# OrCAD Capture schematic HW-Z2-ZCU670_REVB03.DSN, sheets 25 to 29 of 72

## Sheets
25 025 USB UART JTAG: size Custom
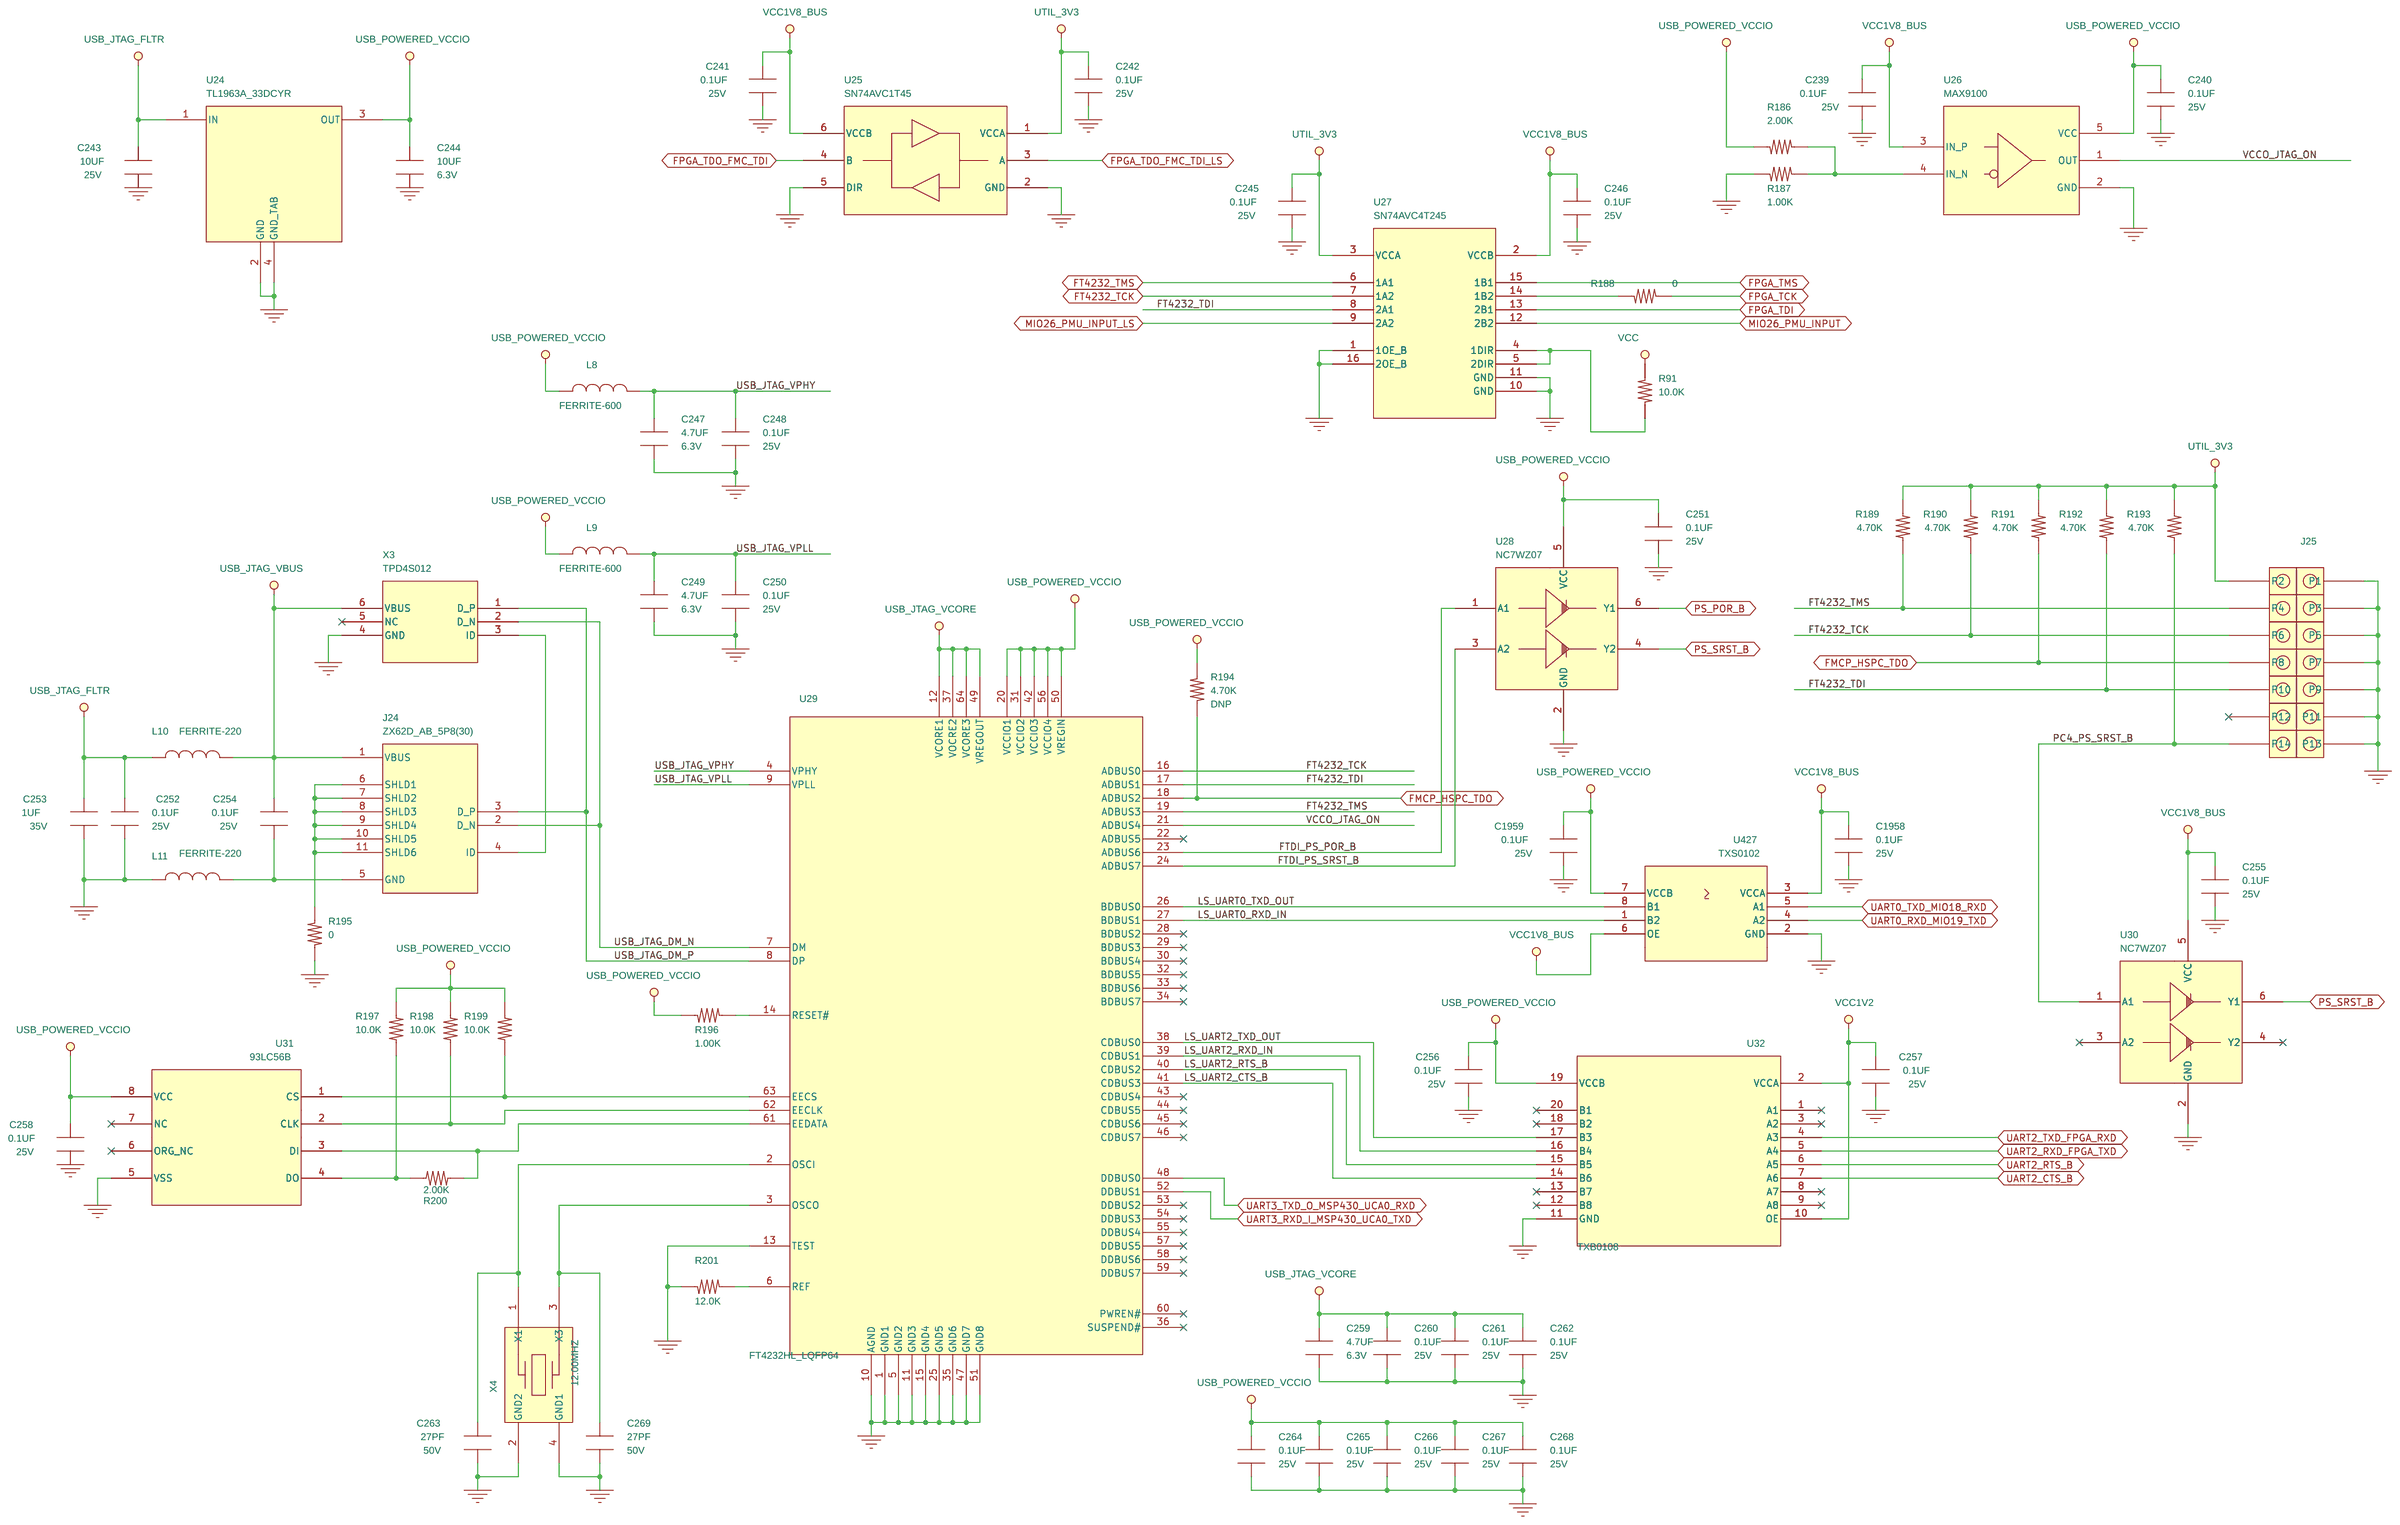
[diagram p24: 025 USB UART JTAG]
26 026 Ethernet RGMII: size Custom
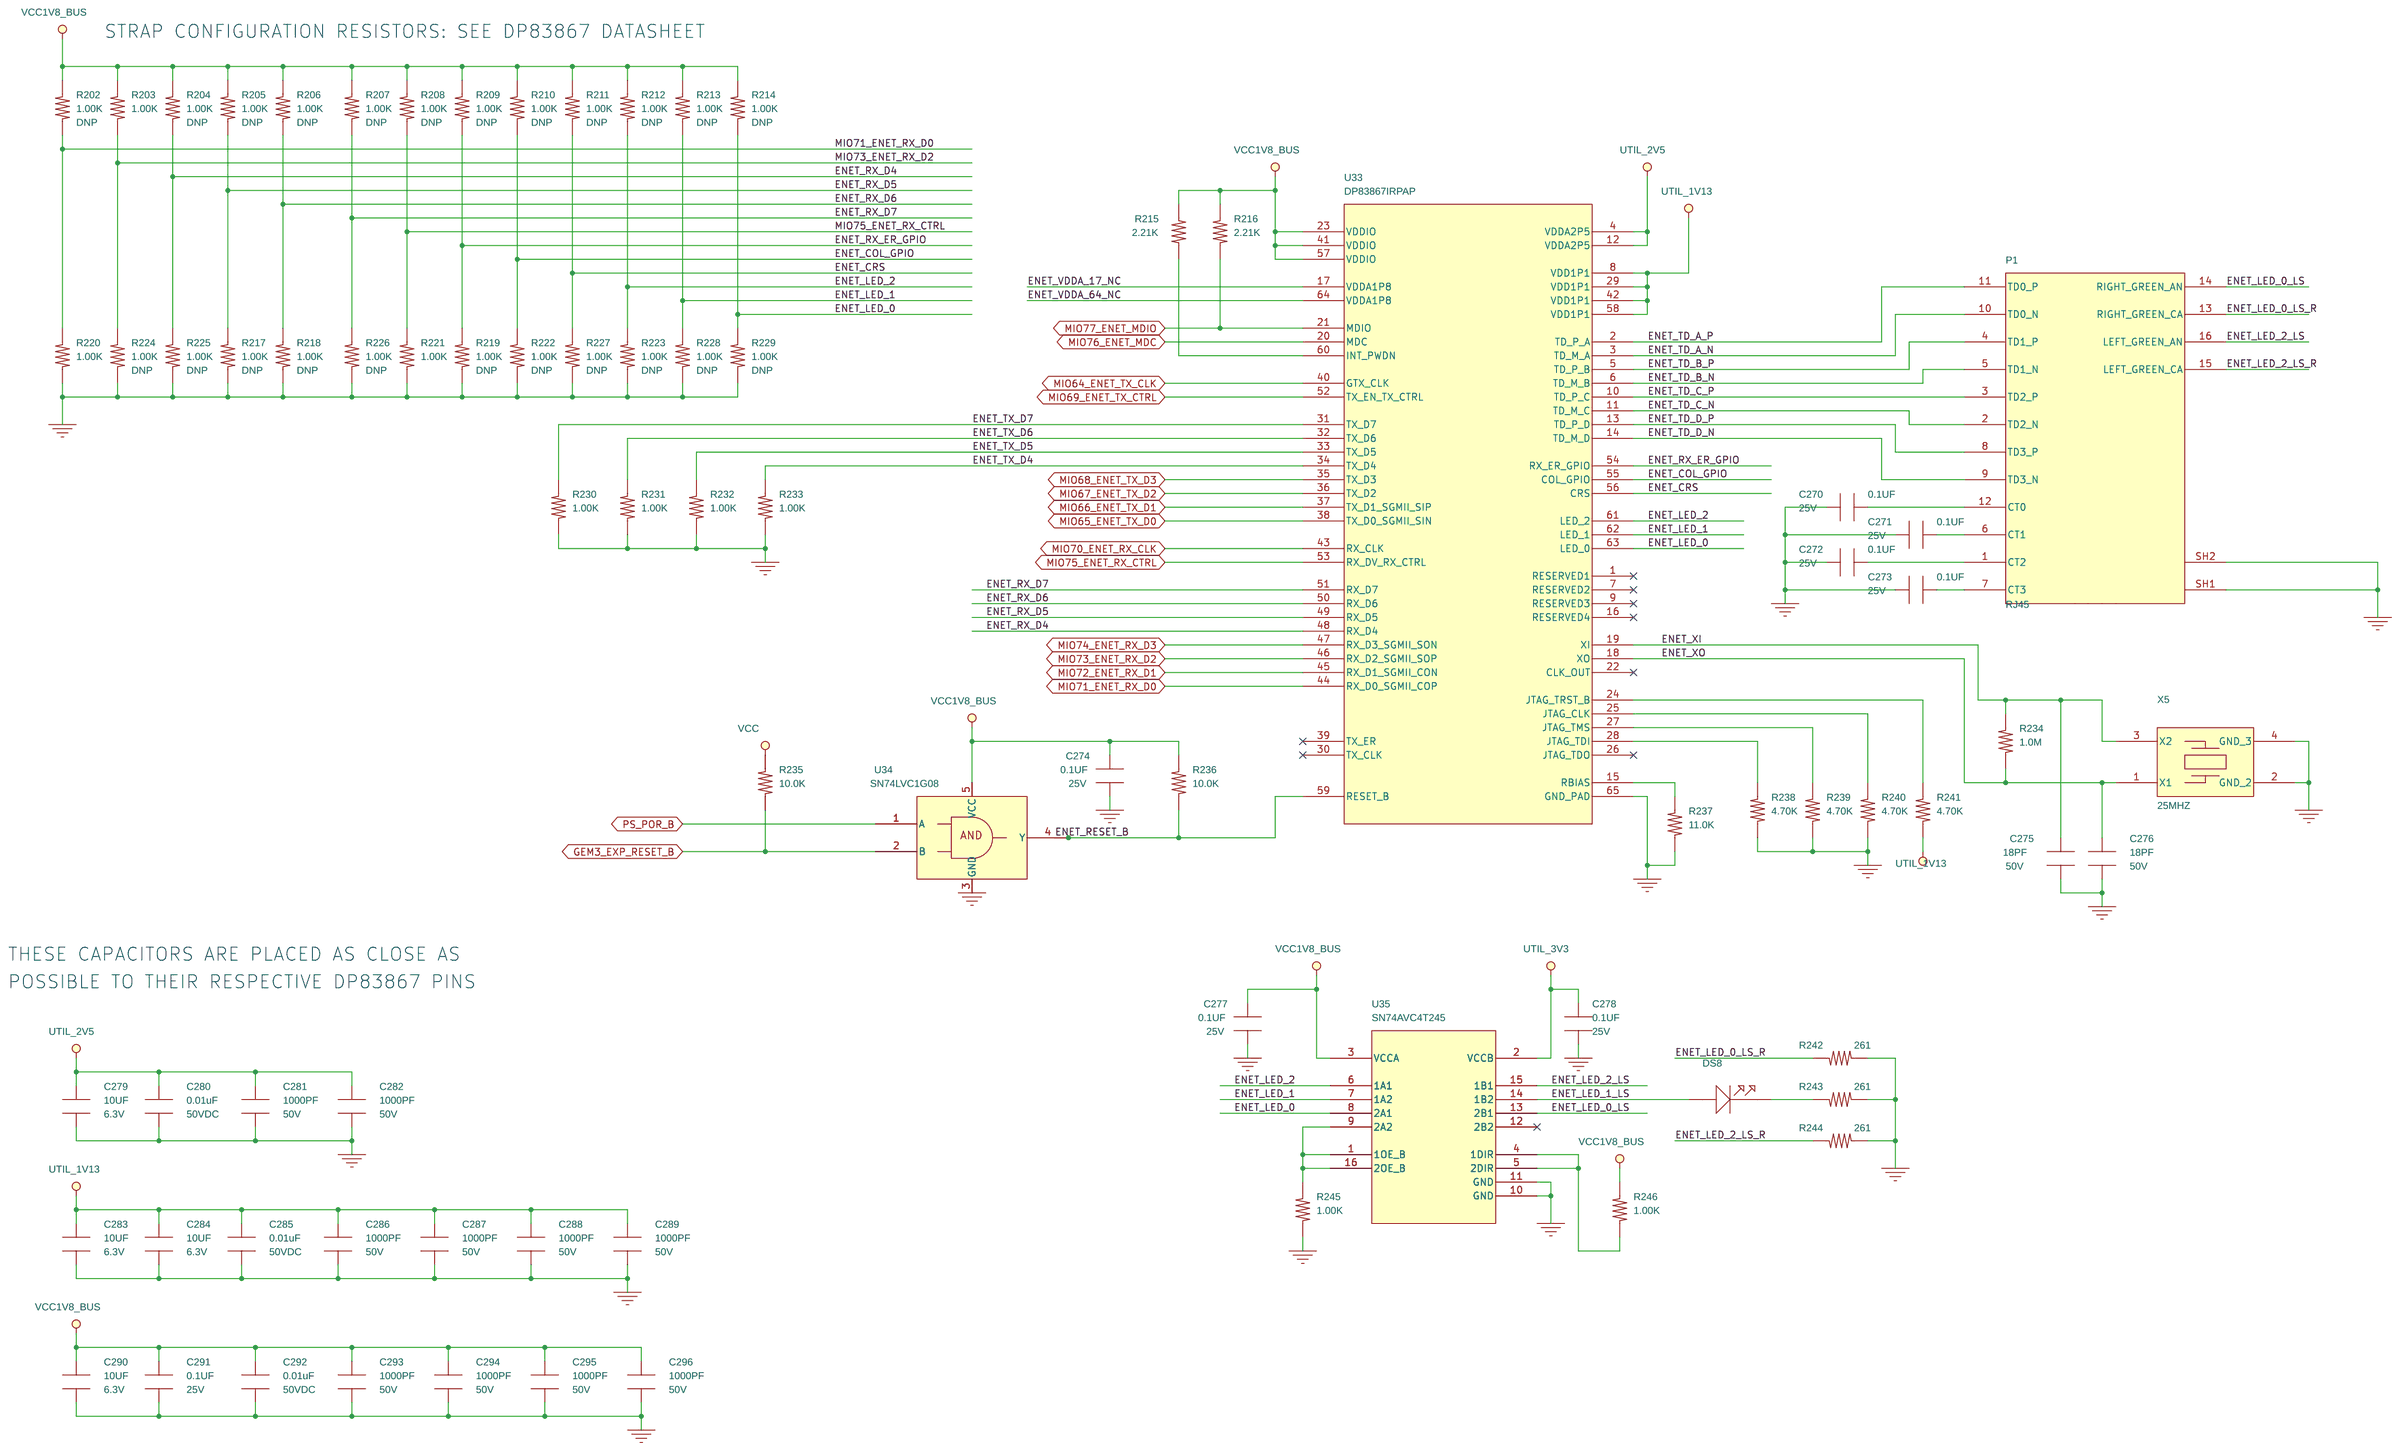
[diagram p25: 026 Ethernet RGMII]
27 027 System Controller: size Custom
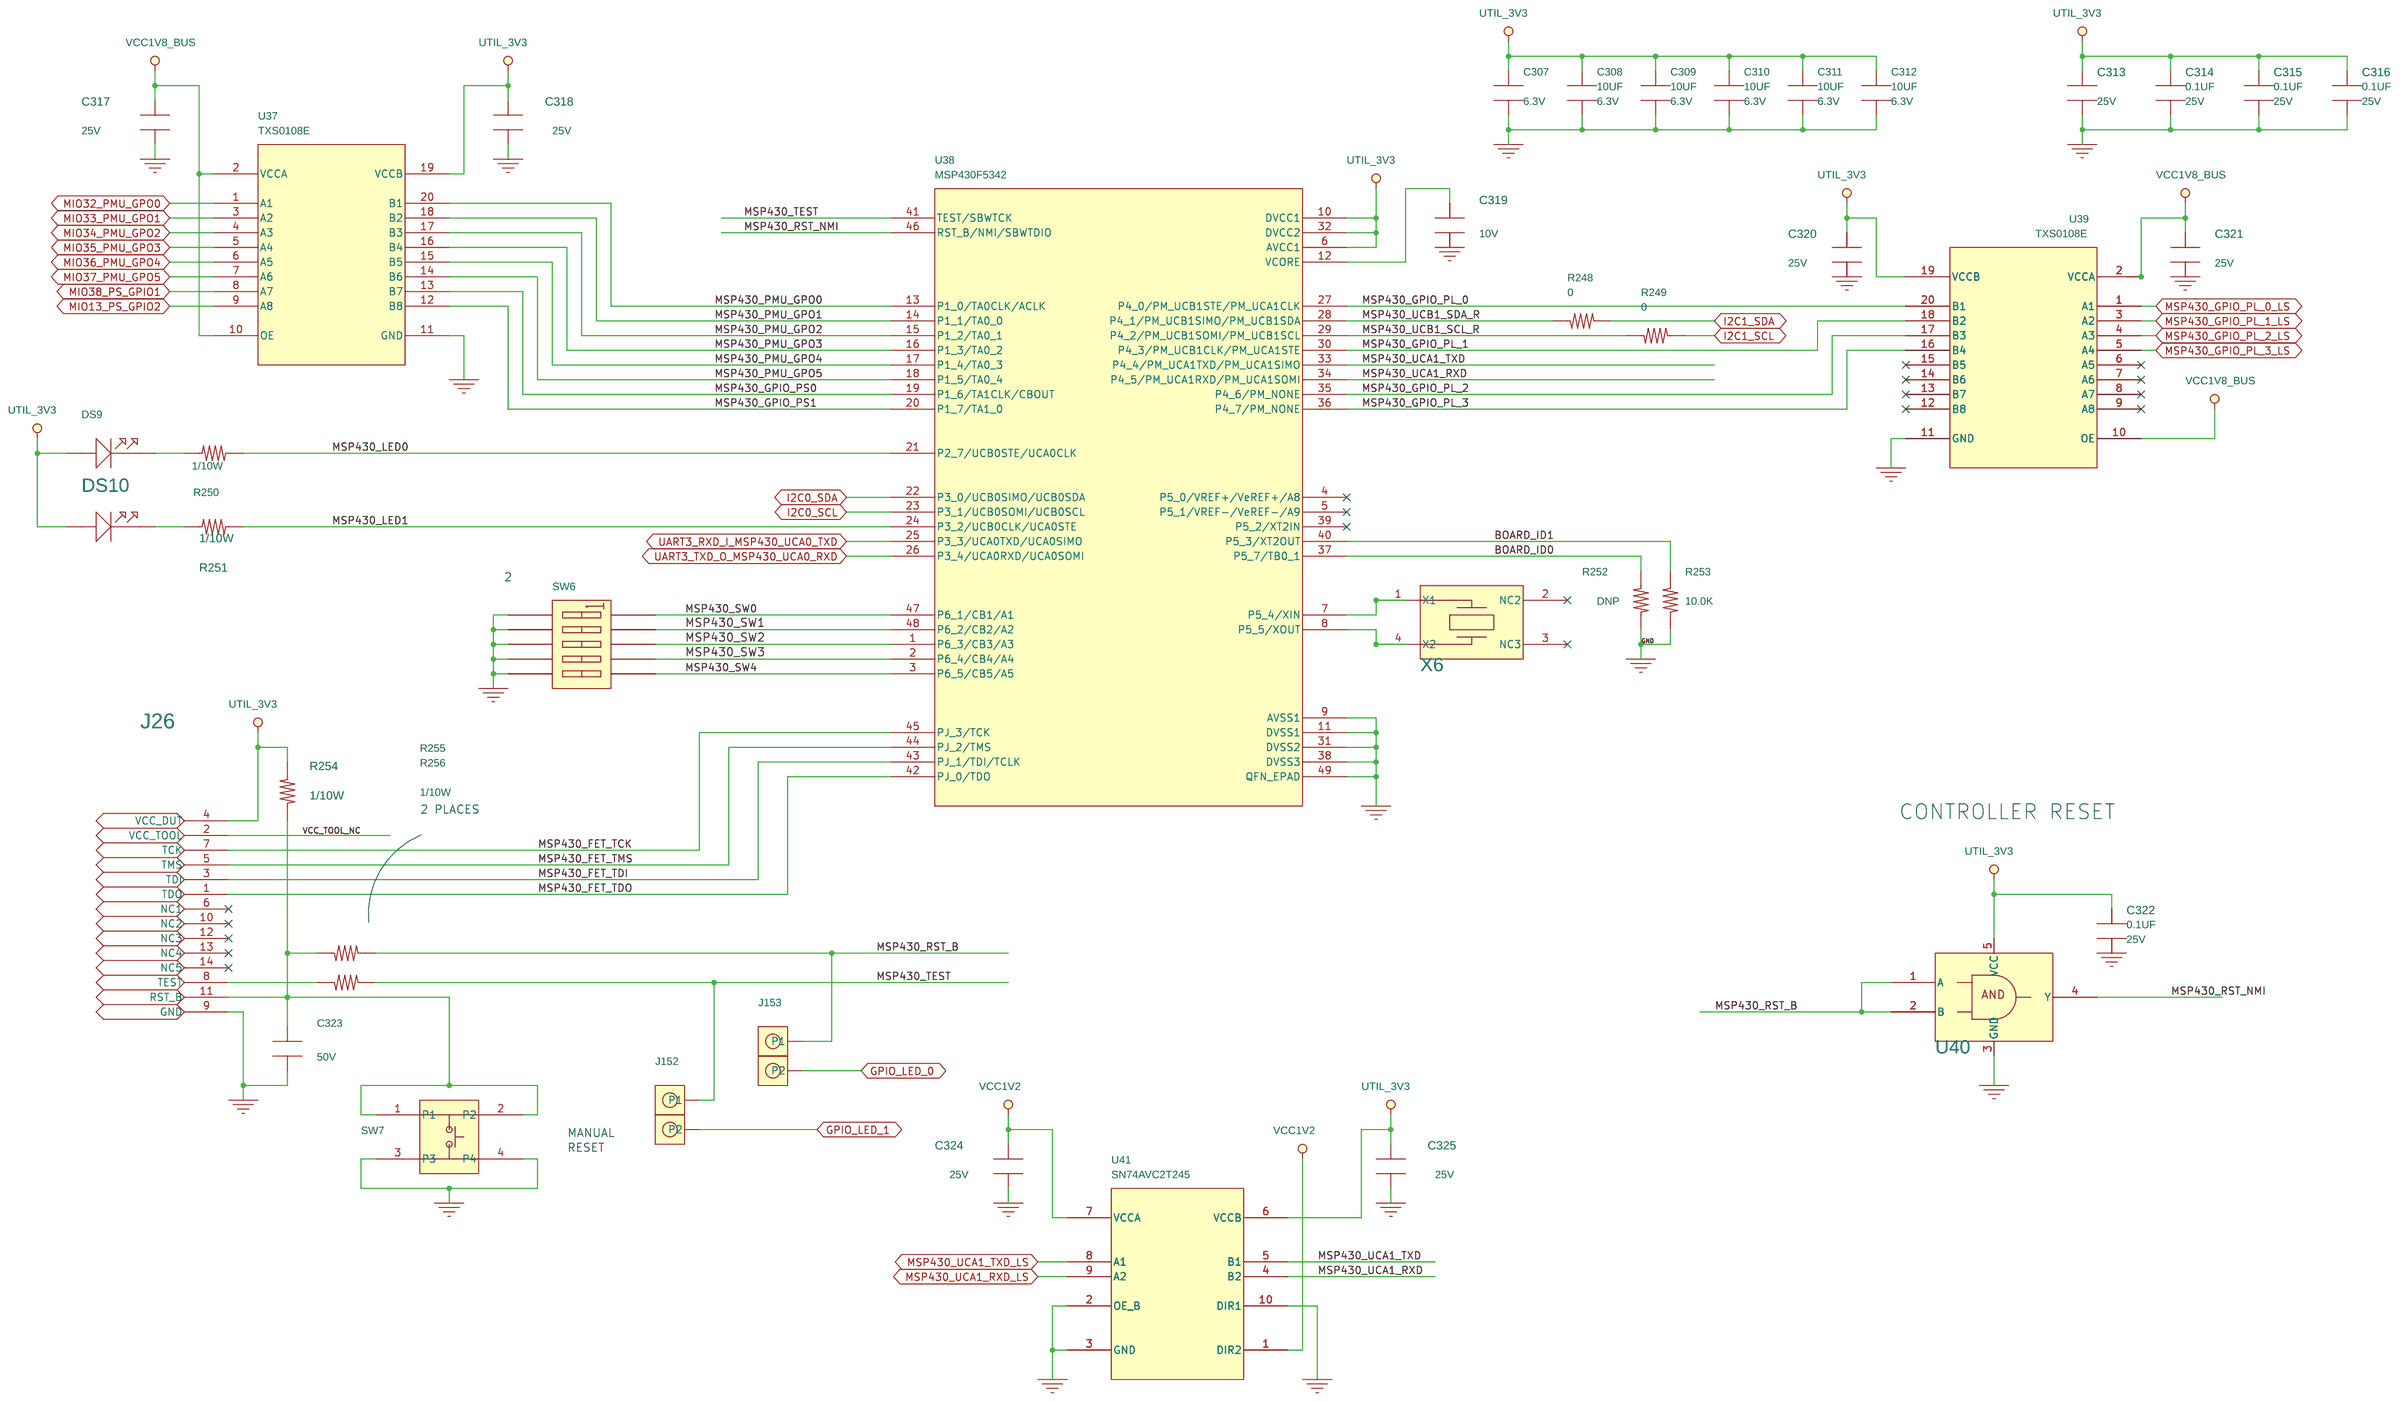
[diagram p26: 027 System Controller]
28 028 FMC HSPC1: size Custom
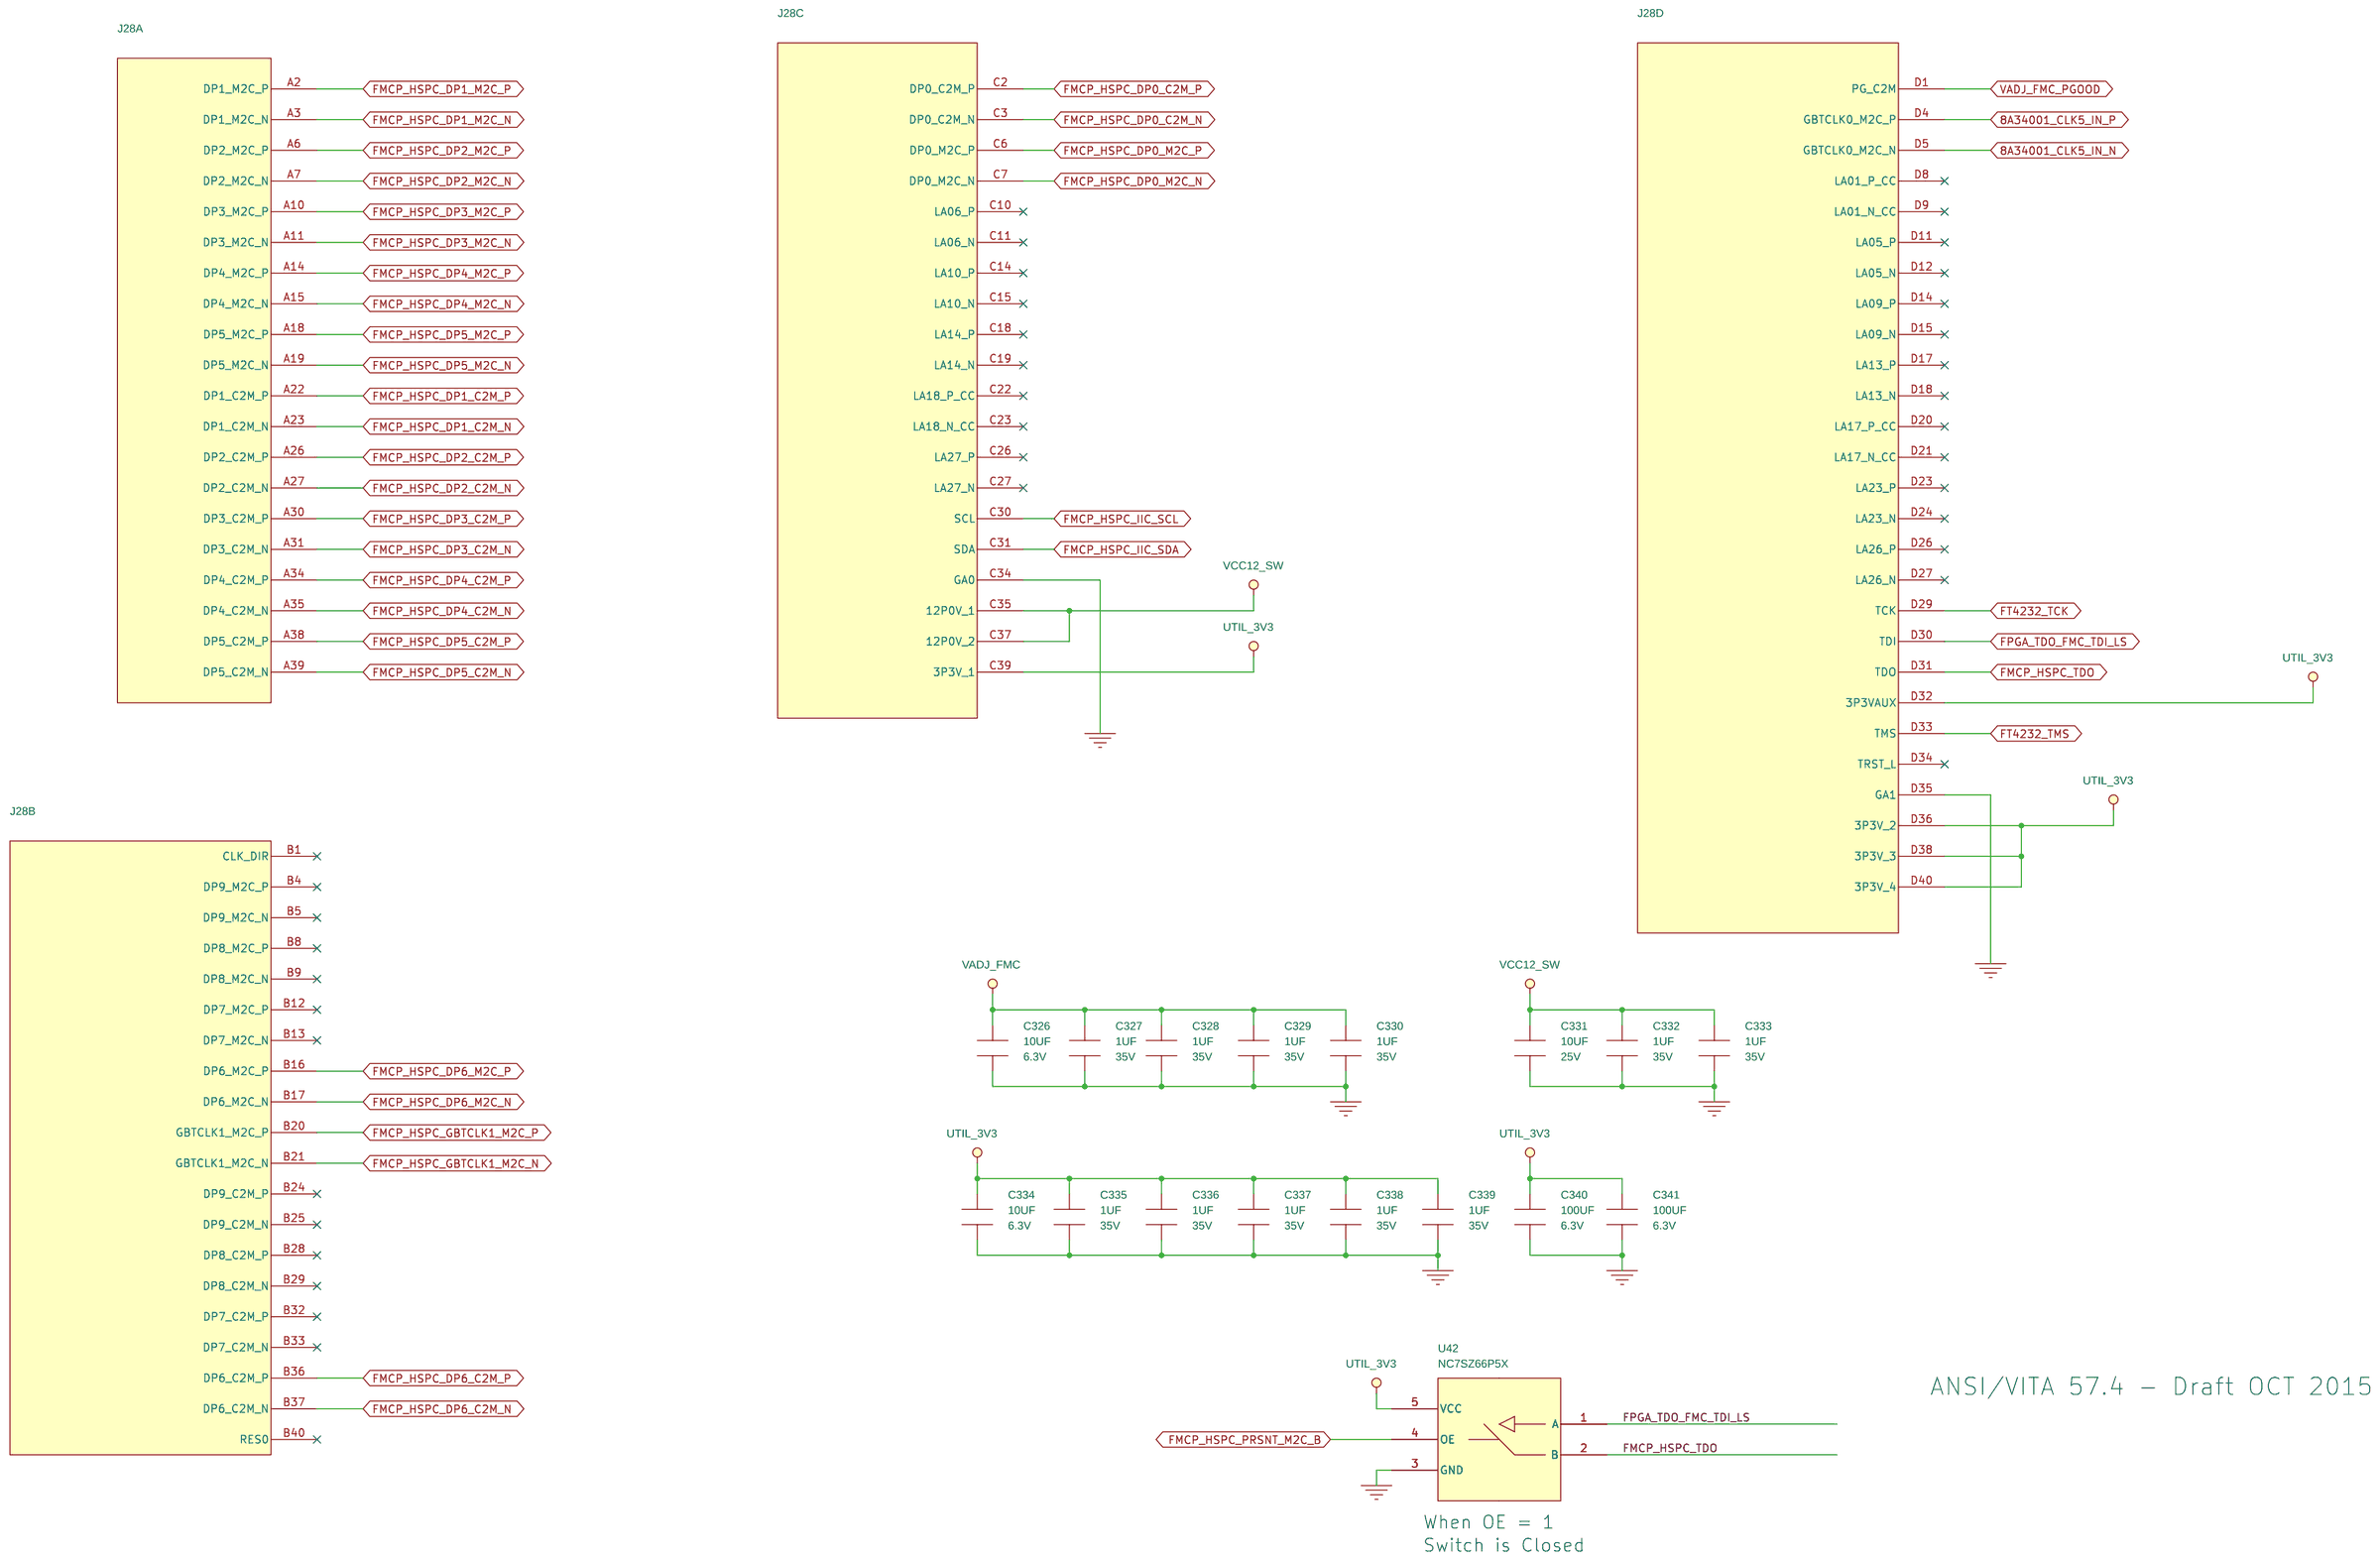
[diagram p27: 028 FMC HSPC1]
29 029 FMC HSPC2: size Custom
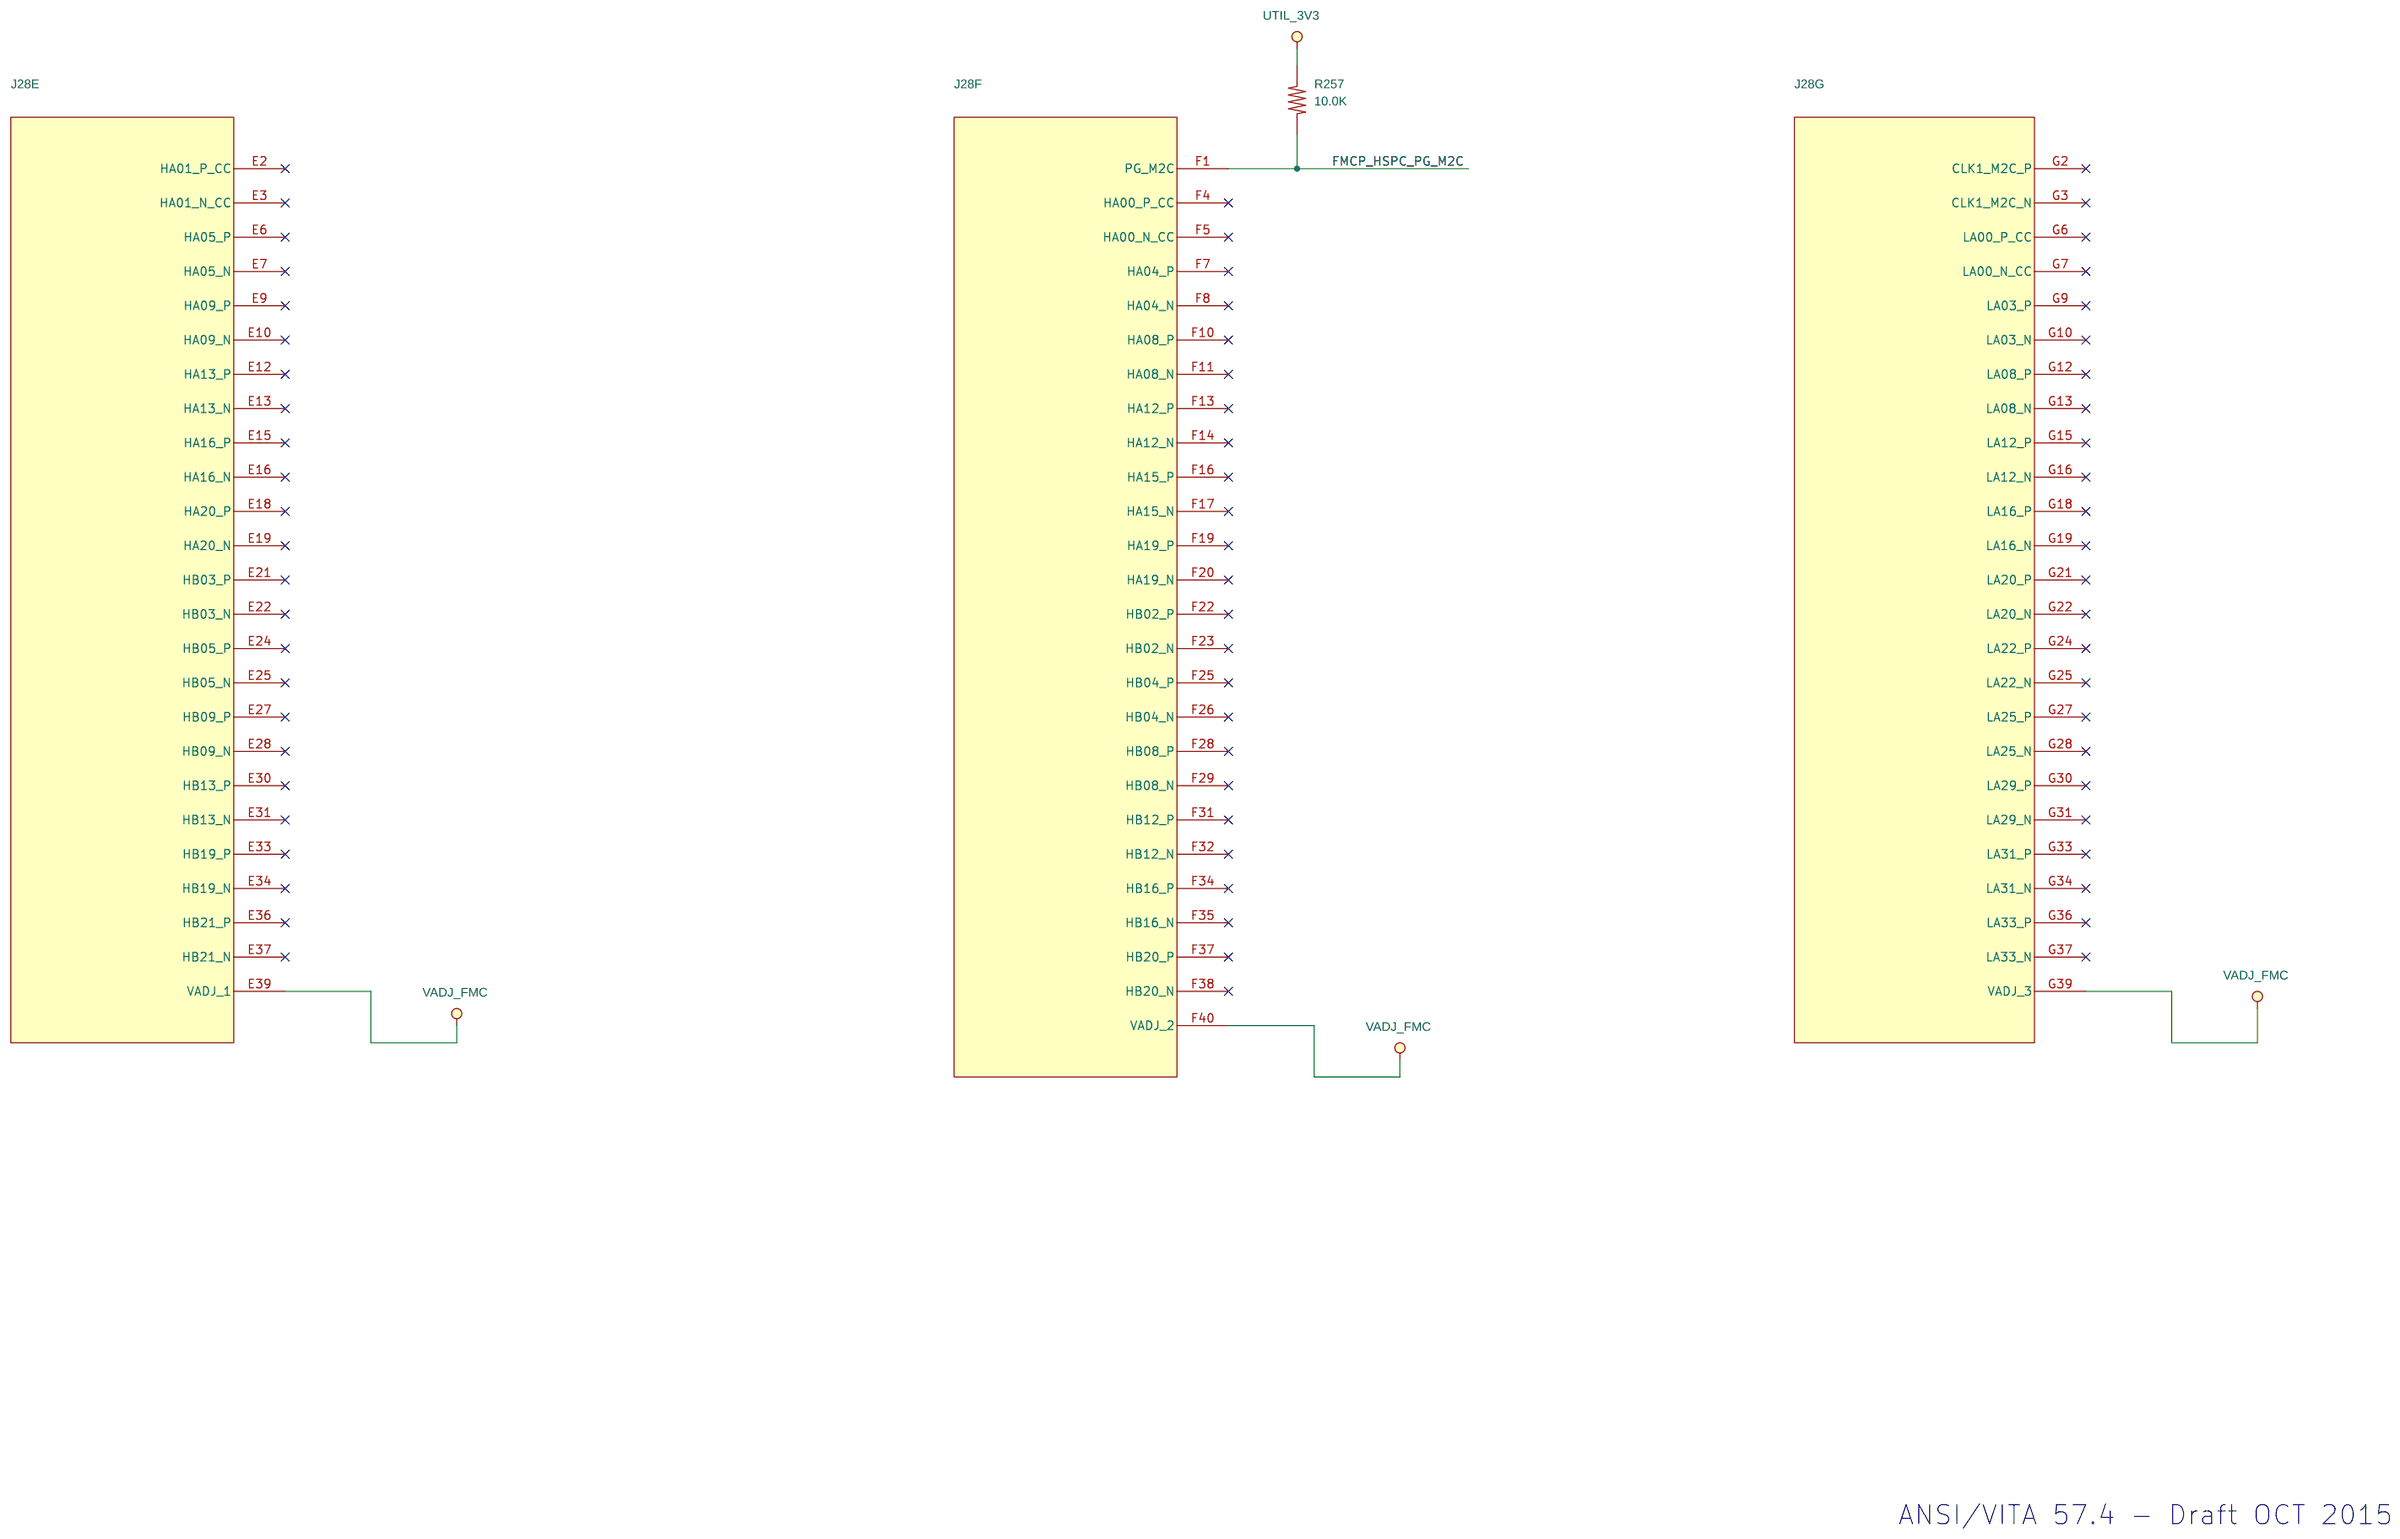
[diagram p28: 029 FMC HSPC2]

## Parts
sheet 025 USB UART JTAG
C239  0.1UF  [CAPC100X50X55]
C240  0.1UF  [CAPC100X50X55]
C241  0.1UF  [CAPC100X50X55]
C242  0.1UF  [CAPC100X50X55]
C243  10UF  [CAPC320X250X220]
C244  10UF  [CAPC100X50X70]
C245  0.1UF  [CAPC100X50X55]
C246  0.1UF  [CAPC100X50X55]
C247  4.7UF  [CAPC100X50X60]
C248  0.1UF  [CAPC100X50X55]
C249  4.7UF  [CAPC100X50X60]
C250  0.1UF  [CAPC100X50X55]
C251  0.1UF  [CAPC100X50X55]
C252  0.1UF  [CAPC100X50X55]
C253  1UF  [CAPC100X50X60]
C254  0.1UF  [CAPC100X50X55]
C255  0.1UF  [CAPC100X50X55]
C256  0.1UF  [CAPC100X50X55]
C257  0.1UF  [CAPC100X50X55]
C258  0.1UF  [CAPC100X50X55]
C259  4.7UF  [CAPC100X50X60]
C260  0.1UF  [CAPC100X50X55]
C261  0.1UF  [CAPC100X50X55]
C262  0.1UF  [CAPC100X50X55]
C263  27PF  [CAPC100X50X55]
C264  0.1UF  [CAPC100X50X55]
C265  0.1UF  [CAPC100X50X55]
C266  0.1UF  [CAPC100X50X55]
C267  0.1UF  [CAPC100X50X55]
C268  0.1UF  [CAPC100X50X55]
C269  27PF  [CAPC100X50X55]
C1958  0.1UF  [CAPC100X50X55]
C1959  0.1UF  [CAPC100X50X55]
J24  ZX62D_AB_5P8(30)  [CON_HR_ZX62D_AB_5P8]
J25  87832-1420  [87832_1420]
L8  FERRITE-600  [INDC200X125X110]
L9  FERRITE-600  [INDC200X125X110]
L10  FERRITE-220  [INDC160X80X95]
L11  FERRITE-220  [INDC160X80X95]
R91  10.0K  [RESC100X50X40]
R186  2.00K  [RESC100X50X40]
R187  1.00K  [RESC100X50X40]
R188  0  [RESC100X50X40]
R189  4.70K  [RESC100X50X40]
R190  4.70K  [RESC100X50X40]
R191  4.70K  [RESC100X50X40]
R192  4.70K  [RESC100X50X40]
R193  4.70K  [RESC100X50X40]
R194  4.70K  [RESC100X50X40]
R195  0  [RESC100X50X40]
R196  1.00K  [RESC100X50X40]
R197  10.0K  [RESC100X50X40]
R198  10.0K  [RESC100X50X40]
R199  10.0K  [RESC100X50X40]
R200  2.00K  [RESC100X50X40]
R201  12.0K  [RESC100X50X40]
U24  TL1963A_33DCYR  [DCY_R_DPSO_G4]
U25  SN74AVC1T45  [SC70_6]
U26  MAX9100  [SOP095P280X145_5]
U27  SN74AVC4T245  [QFN_RSV_16]
U28  NC7WZ07  [SC70_6]
U29  FT4232HL_LQFP64  [LQFP_64]
U30  NC7WZ07  [SC70_6]
U31  93LC56B  [SOIC8P127W390]
U32  TXB0108  [TSSOP_20]
U427  TXS0102  [soic50p320x90x8]
X3  TPD4S012  [DRY_6_SON]
X4  12.00MHZ  [xtal_320x250X71]
sheet 026 Ethernet RGMII
C270  0.1UF  [CAPC100X50X55]
C271  0.1UF  [CAPC100X50X55]
C272  0.1UF  [CAPC100X50X55]
C273  0.1UF  [CAPC100X50X55]
C274  0.1UF  [CAPC100X50X55]
C275  18PF  [CAPC100X50X50]
C276  18PF  [CAPC100X50X50]
C277  0.1UF  [CAPC100X50X55]
C278  0.1UF  [CAPC100X50X55]
C279  10UF  [CAPC100X50X70]
C280  0.01uF  [CAPC100X50X55]
C281  1000PF  [CAPC100X50X55]
C282  1000PF  [CAPC100X50X55]
C283  10UF  [CAPC100X50X70]
C284  10UF  [CAPC100X50X70]
C285  0.01uF  [CAPC100X50X55]
C286  1000PF  [CAPC100X50X55]
C287  1000PF  [CAPC100X50X55]
C288  1000PF  [CAPC100X50X55]
C289  1000PF  [CAPC100X50X55]
C290  10UF  [CAPC100X50X70]
C291  0.1UF  [CAPC100X50X55]
C292  0.01uF  [CAPC100X50X55]
C293  1000PF  [CAPC100X50X55]
C294  1000PF  [CAPC100X50X55]
C295  1000PF  [CAPC100X50X55]
C296  1000PF  [CAPC100X50X55]
DS8  LED-GRN-SMT  [LED_0603]
P1  RJ45  [CON_WURTH_7499111221A]
R202  1.00K  [RESC100X50X40]
R203  1.00K  [RESC100X50X40]
R204  1.00K  [RESC100X50X40]
R205  1.00K  [RESC100X50X40]
R206  1.00K  [RESC100X50X40]
R207  1.00K  [RESC100X50X40]
R208  1.00K  [RESC100X50X40]
R209  1.00K  [RESC100X50X40]
R210  1.00K  [RESC100X50X40]
R211  1.00K  [RESC100X50X40]
R212  1.00K  [RESC100X50X40]
R213  1.00K  [RESC100X50X40]
R214  1.00K  [RESC100X50X40]
R215  2.21K  [RESC100X50X40]
R216  2.21K  [RESC100X50X40]
R217  1.00K  [RESC100X50X40]
R218  1.00K  [RESC100X50X40]
R219  1.00K  [RESC100X50X40]
R220  1.00K  [RESC100X50X40]
R221  1.00K  [RESC100X50X40]
R222  1.00K  [RESC100X50X40]
R223  1.00K  [RESC100X50X40]
R224  1.00K  [RESC100X50X40]
R225  1.00K  [RESC100X50X40]
R226  1.00K  [RESC100X50X40]
R227  1.00K  [RESC100X50X40]
R228  1.00K  [RESC100X50X40]
R229  1.00K  [RESC100X50X40]
R230  1.00K  [RESC100X50X40]
R231  1.00K  [RESC100X50X40]
R232  1.00K  [RESC100X50X40]
R233  1.00K  [RESC100X50X40]
R234  1.0M  [RESC100X50X40]
R235  10.0K  [RESC100X50X40]
R236  10.0K  [RESC100X50X40]
R237  11.0K  [RESC100X50X40]
R238  4.70K  [RESC100X50X40]
R239  4.70K  [RESC100X50X40]
R240  4.70K  [RESC100X50X40]
R241  4.70K  [RESC100X50X40]
R242  261  [RESC100X50X40]
R243  261  [RESC100X50X40]
R244  261  [RESC100X50X40]
R245  1.00K  [RESC100X50X40]
R246  1.00K  [RESC100X50X40]
U33  DP83867IRPAP  [HTQFP05P12X12X120_64_390]
U34  SN74LVC1G08  [SC70_5]
U35  SN74AVC4T245  [QFN_RSV_16]
X5  25MHZ  [XTAL_EPSON_FA238]
sheet 027 System Controller
C307  10UF  [CAPC100X50X70]
C308  10UF  [CAPC100X50X70]
C309  10UF  [CAPC100X50X70]
C310  10UF  [CAPC100X50X70]
C311  10UF  [CAPC100X50X70]
C312  10UF  [CAPC100X50X70]
C313  0.1UF  [CAPC100X50X55]
C314  0.1UF  [CAPC100X50X55]
C315  0.1UF  [CAPC100X50X55]
C316  0.1UF  [CAPC100X50X55]
C317  0.1UF  [CAPC100X50X55]
C318  0.1UF  [CAPC100X50X55]
C319  0.47UF  [CAPC100X50X55]
C320  0.1UF  [CAPC100X50X55]
C321  0.1UF  [CAPC100X50X55]
C322  0.1UF  [CAPC100X50X55]
C323  2200PF  [CAPC100X50X55]
C324  0.1UF  [CAPC100X50X55]
C325  0.1UF  [CAPC100X50X55]
DS9  LED-BLUE-SMT  [LED_0805]
DS10  LED-GRN-SMT  [LED_0603]
J26  103308-2  [CON_0_100_14]
J152  HDR_1X2  [HDR_1X2]
J153  HDR_1X2  [HDR_1X2]
R248  0  [RESC100X50X40]
R249  0  [RESC100X50X40]
R250  261  [RESC100X50X40]
R251  261  [RESC100X50X40]
R252  10.0K  [RESC100X50X40]
R253  10.0K  [RESC100X50X40]
R254  47.5K  [RESC100X50X40]
R255  0  [RESC100X50X40]
R256  0  [RESC100X50X40]
SW6  DIP5SMTHP  [SW_WURTH_5POS_HALF_PITCH]
SW7  TL3301EF100QG  [SW_TL3301_G_4P]
U37  TXS0108E  [TSSOP_20]
U38  MSP430F5342  [VQFN05P700X700X100_48_515]
U39  TXS0108E  [TSSOP_20]
U40  SN74LVC1G08  [SC70_5]
U41  SN74AVC2T245  [QFN40P140X180X55-10]
X6  32.768KHZ  [XTAL_MC306]
sheet 028 FMC HSPC1
C326  10UF  [CAPC100X50X70]
C327  1UF  [CAPC100X50X60]
C328  1UF  [CAPC100X50X60]
C329  1UF  [CAPC100X50X60]
C330  1UF  [CAPC100X50X60]
C331  10UF  [CAPC320X250X220]
C332  1UF  [CAPC100X50X60]
C333  1UF  [CAPC100X50X60]
C334  10UF  [CAPC100X50X70]
C335  1UF  [CAPC100X50X60]
C336  1UF  [CAPC100X50X60]
C337  1UF  [CAPC100X50X60]
C338  1UF  [CAPC100X50X60]
C339  1UF  [CAPC100X50X60]
C340  100UF  [CAPC320X160X180]
C341  100UF  [CAPC320X160X180]
U42  NC7SZ66P5X  [SC70_5]
sheet 029 FMC HSPC2
R257  10.0K  [RESC100X50X40]
sheet 031 FMC HSPC4
J28  ASP_184329_01  [ASP_184329_01]  (sections A,B,C,D,E,F,G,H,I,J,K,L,M,N,O,P)

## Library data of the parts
C239-C242 C245 C246 C248 C250-C252 C254-C258 C260-C262 C264-C268 C270-C274 C277 C278 C291 C1958 C1959 = CAP_NP: Cap Cer 100nF 10% 25V X5R 0402; ALT_SYMBOLS: CAPC100X50X55RND; Agile Part Number: CAP-00068-01; CIP Link: http://xsjbrdwin1/CIP-E/Component/Index/All?pn=100040; Dielectric Type: X5R; OWNER: 4001; PRICE: 0.01; Part Type: CERAMIC; PartType: CERAMIC; ROHS: Yes; Tolerance: 10%; Voltage: 25V; barcode: 100040
C243 = CAP_NP: Cap Cer 10uF 10% 25V X5R 1210; ALT_SYMBOLS: CAPC320X250X220RND; Agile Part Number: CAP-00113-01; CIP Link: http://xsjbrdwin1/CIP-E/Component/Index/All?pn=100123; Dielectric Type: X5R; OWNER: 3670; PRICE: 0.04; Part Type: CERAMIC; PartType: CERAMIC; ROHS: Yes; Tolerance: 10%; Voltage: 25V; barcode: 100123
C244 C279 C283 C284 C290 C326 C334 = CAP_NP: Cap Cer 10uF 20%  6.3V X6S 0402; ALT_SYMBOLS: CAPC100X50X55RND; Agile Part Number: CAP-00035-01; CIP Link: http://xsjbrdwin1/CIP-E/Component/Index/All?pn=100268; Dielectric Type: X6S; OWNER: 3670; PRICE: 0.04; Part Type: CERAMIC; PartType: CERAMIC; ROHS: Yes; Tolerance: 20%; Voltage: 6.3V; barcode: 100268
C247 C249 C259 = CAP_NP: Cap Cer 4.7uF 20% 6.3V X5R 0402; ALT_SYMBOLS: CAPC100X50X60RND; Agile Part Number: CAP-00085-01; CIP Link: http://xsjbrdwin1/CIP-E/Component/Index/All?pn=100067; Dielectric Type: X5R; OWNER: 3709; PRICE: 0.06; Part Type: CERAMIC; PartType: CERAMIC; ROHS: Yes; Tolerance: 20%; Voltage: 6.3V; barcode: 100067
C253 = CAP_NP: Cap Cer 1uF 10% 35V X5R 0402; ALT_SYMBOLS: CAPC100X50X60RND; Agile Part Number: CAP-00165-01; CIP Link: http://xsjbrdwin1/CIP-E/Component/Index/All?pn=100192; Dielectric Type: X5R; OWNER: 4001; PRICE: 0.01; Part Type: CERAMIC; PartType: CERAMIC; ROHS: Yes; Tolerance: 10%; Voltage: 35V; barcode: 100192
C263 C269 = CAP_NP: Cap Cer 27pF 5% 50V C0G 0402; ALT_SYMBOLS: CAPC100X50X55RND; Agile Part Number: CAP-00037-01; CIP Link: http://xsjbrdwin1/CIP-E/Component/Index/All?pn=100217; Dielectric Type: NP0; OWNER: 3670; PRICE: 0.01; Part Type: CERAMIC; PartType: CERAMIC; ROHS: Yes; Tolerance: 5%; Voltage: 50V; barcode: 100217
J24 = CONN_USB_MICRO_B_TH: Conn Rcpt Micro USB 2.0 Type AB RA 0.65mm P Gray SMT/TH; Agile Part Number: CON-00008-01; Barcode: 400014; CIP Link: http://xsjbrdwin1/CIP-E/Component/Index/All?pn=400014; OWNER: 13503; PRICE: 0.43; Part Type: RECEPTACLE; PartType: RECEPTACLE; Pins: 5PIN; ROHS: Yes
J25 = HDR_2X7: Conn Hdr Male Vert 14 Pos 2x7 2mm P Black SMT Shrouded with Pegs; Agile Part Number: CON-00111-01; Barcode: 400030; CIP Link: http://xsjbrdwin1/CIP-E/Component/Index/All?pn=400030; OWNER: 4001; PRICE: 1.34; Part Type: RECEPTACLE; PartType: RECEPTACLE; Pins: 14PINS; Pitch: 2MM; ROHS: Yes
L8 L9 = IND: Bead 600R 500mA 300mR 0805; Agile Part Number: FLT-00005-01; Barcode: 300009; CIP Link: http://xsjbrdwin1/CIP-E/Component/Index/All?pn=300009; OWNER: 4001; Part Type: FERRITE; PartType: FERRITE; ROHS: Yes
L10 L11 = IND: Bead 220R 25% 2A 50mR 0603; Agile Part Number: IND-00016-01; Barcode: 300010; CIP Link: http://xsjbrdwin1/CIP-E/Component/Index/All?pn=300010; OWNER: 4001; PRICE: 0.02; Part Type: FERRITE; PartType: FERRITE; ROHS: Yes
R91 R197-R199 R235 R236 R257 = RES: Res 10K 1% 1/16W 100PPM 50V 0402; ALT_SYMBOLS: RESC100X50X40RND; Agile Part Number: RES-00030-01; Barcode: 200025; CIP Link: http://xsjbrdwin1/CIP-E/Component/Index/All?pn=200025; OWNER: 4001; PRICE: 0; Part Type: SMT - 1%; PartType: SMT - 1%; Power: 1/10W; ROHS: Yes; Rated Power: 1/16W; Tolerance: 1%; primarykey: 1
R186 R200 = RES: Res 2K 1% 1/16W 100PPM 50V 0402; ALT_SYMBOLS: RESC100X50X40RND; Agile Part Number: RES-00003-01; Barcode: 200096; CIP Link: http://xsjbrdwin1/CIP-E/Component/Index/All?pn=200096; OWNER: 4001; PRICE: 0.05; Part Type: SMT - 1%; PartType: SMT - 1%; Power: 1/16W; ROHS: Yes; Rated Power: 1/16W; Tolerance: 1%; primarykey: 2
R187 R196 R203 R220 R221 R230-R233 R245 R246 = RES: Res 1K 1% 1/16W 100PPM 50V 0402; ALT_SYMBOLS: RESC100X50X40RND; Agile Part Number: RES-00027-01; Barcode: 200098; CIP Link: http://xsjbrdwin1/CIP-E/Component/Index/All?pn=200098; OWNER: 4001; PRICE: 0; Part Type: SMT - 1%; PartType: SMT - 1%; Power: 1/16W; ROHS: Yes; Rated Power: 1/16W; Tolerance: 1%; primarykey: 7
R188 R195 = RES: Res 0R 50mR 1A 0402; ALT_SYMBOLS: RESC100X50X40RND; Agile Part Number: RES-00010-01; Barcode: 200012; CIP Link: http://xsjbrdwin1/CIP-E/Component/Index/All?pn=200012; OWNER: 4001; PRICE: 0.01; Part Type: SMT - 5%; PartType: SMT - 5%; Power: 1/10W; ROHS: Yes; Tolerance: 5%; primarykey: 13
R189-R193 R238-R241 = RES: Res 4K7 1% 1/16W 100PPM 50V 0402; ALT_SYMBOLS: RESC100X50X40RND; Agile Part Number: RES-00035-01; Barcode: 200067; CIP Link: http://xsjbrdwin1/CIP-E/Component/Index/All?pn=200067; OWNER: 3670; PRICE: 0.01; Part Type: SMT - 1%; PartType: SMT - 1%; Power: 1/16W; ROHS: Yes; Rated Power: 1/16W; Tolerance: 1%; primarykey: 128
R194 = RES: Res 4K7 1% 1/16W 100PPM 50V 0402; ALT_SYMBOLS: RESC100X50X40RND; ASSEMBLY_OPTIONS: DNP; Agile Part Number: RES-00035-01; Barcode: 200067; CIP Link: http://xsjbrdwin1/CIP-E/Component/Index/All?pn=200067; OWNER: 3709; PRICE: 0; Part Type: SMT - 1%; PartType: SMT - DNP; Power: DNP; ROHS: Yes; Rated Power: 1/16W; Tolerance: 1%; primarykey: 73
R201 = RES: Res 12K 1% 1/16W 100PPM 50V 0402; ALT_SYMBOLS: RESC100X50X40RND; Agile Part Number: RES-00349-01; Barcode: 200386; CIP Link: http://xsjbrdwin1/CIP-E/Component/Index/All?pn=200386; OWNER: 14716; PRICE: 0; Part Type: SMT - 1%; PartType: SMT - 1%; Power: 1/10W; ROHS: Yes; Rated Power: 1/16W; Tolerance: 1%; primarykey: 190
U24 = TL1963A_33DCYR: IC LDO 20V 1.5A 3.3V SOT223-4; Agile Part Number: ICS-00006-01; Barcode: 500400; CIP Link: http://xsjbrdwin1/CIP-E/Component/Index/All?pn=500400; Family: REGULATOR; Part Type: REGULATOR; ROHS: Yes
U25 = SN74AVC1T45: IC Lvl Trans 1-Bit 500Mbps 1.2-3.6V 12mA SC70-6; Agile Part Number: ICS-00084-01; Barcode: 500060; CIP Link: http://xsjbrdwin1/CIP-E/Component/Index/All?pn=500060; Family: BUS TRANSCEIVER; Part Type: BUS TRANSCEIVER; ROHS: Yes
U26 = MAX9100: IC Comp Single 10mV Vios 2mV Vihyst 4uSec SOT23-5; Agile Part Number: ICS-00096-01; Barcode: 500080; CIP Link: http://xsjbrdwin1/CIP-E/Component/Index/All?pn=500080; Family: COMPARATOR; Part Type: COMPARATOR; ROHS: Yes
U27 U35 = SN74AVC4T245: IC Lvl Trans 4-Bit Bidir 380Mbps 1.2-3.6V 50mA UQFN-16; Agile Part Number: ICS-00049-01; Barcode: 500013; CIP Link: http://xsjbrdwin1/CIP-E/Component/Index/All?pn=500013; Family: BUS TRANSCEIVER; Part Type: BUS TRANSCEIVER; ROHS: Yes
U28 U30 = NC7WZ07: IC Buffer Dual 5V 50mA 3.9nSec SC70-6 Open Drain; Agile Part Number: ICS-00102-01; Barcode: 500086; CIP Link: http://xsjbrdwin1/CIP-E/Component/Index/All?pn=500086; Family: CMOS LOGIC; Part Type: CMOS LOGIC; ROHS: Yes
U29 = FT4232HL: IC PHY USB 2.0 HS Single 480Mbps 3.3V 4-UART/MPSSE LQFP-64; Agile Part Number: ICS-00337-01; Barcode: 500498; CIP Link: http://xsjbrdwin1/CIP-E/Component/Index/All?pn=500498; Family: USB TO UART, JTAG; Part Type: USB TO UART, JTAG; ROHS: YES
U31 = 93LC56B: IC EEPROM 2Kb 128x16-Bit Serial 2MHz 2.5V SOIC-8; Agile Part Number: ICS-00335-01; Barcode: 500495; CIP Link: http://xsjbrdwin1/CIP-E/Component/Index/All?pn=500495; Family: MEMORY; Part Type: MEMORY; ROHS: YES
U32 = TXB0108: IC TRNSLTR BIDIRECTIONAL 20TSSOP; Agile Part Number: ICS-00087-01; Barcode: 500063; CIP Link: http://xsjbrdwin1/CIP-E/Component/Index/All?pn=500063; Part Type: LEVEL TRANSLATOR
U427 = TXS0102: IC TRNSLTR BIDIRECTIONAL US8; Agile Part Number: ICS-00139-01; Barcode: 500148; CIP Link: http://xsjbrdwin1/CIP-E/Component/Index/All?pn=500148; Part Type: LEVEL TRANSLATOR
X3 = TPD4S012: TVSD 4-Ch 5.5V 3A 60W SON-6 10KV Contact Discharge; Agile Part Number: ICS-00003-01; Barcode: 500251; CIP Link: http://xsjbrdwin1/CIP-E/Component/Index/All?pn=500251; Family: ESD PROTECTOR; OWNER: 3501; PRICE: 0; Part Type: ESD PROTECTOR; PartType: ZENER; Power: 60MW; ROHS: Yes
X4 = ABM8_XTAL: Xtal 12MHz 200uW 100R 18pF 52PPM 3225; Agile Part Number: XTL-00043-01; Barcode: 60000019; CIP Link: http://xsjbrdwin1/CIP-E/Component/Index/All?pn=60000019; Frequency Stability: 30 ppm; Frequency Tolerance: 20 ppm; Load Capacitance: 18pF; Part Type: CRYSTAL
C275 C276 = CAP_NP: Cap Cer 18pF 2% 50% C0G 0402; ALT_SYMBOLS: CAPC100X50X50RND; Agile Part Number: CAP-00084-01; CIP Link: http://xsjbrdwin1/CIP-E/Component/Index/All?pn=100065; Dielectric Type: NPO; OWNER: 3709; PRICE: 0; Part Type: CERAMIC; PartType: CERAMIC; ROHS: Yes; Tolerance: 5%; Voltage: 50V; barcode: 100065
C280 C285 C292 = CAP_NP: Cap Cer 10nF 10% 50V X7R 0402; ALT_SYMBOLS: CAPC100X50X55RND; Agile Part Number: CAP-00031-01; CIP Link: http://xsjbrdwin1/CIP-E/Component/Index/All?pn=100003; Dielectric Type: X7R; OWNER: 4001; PRICE: 0; Part Type: CERAMIC; PartType: CERAMIC; ROHS: Yes; Tolerance: 10%; Voltage: 50VDC; barcode: 100003
C281 C282 C286-C289 C293-C296 = CAP_NP: Cap Cer 1nF 10% 50V X7R 0402; ALT_SYMBOLS: CAPC100X50X55RND; Agile Part Number: CAP-00036-01; CIP Link: http://xsjbrdwin1/CIP-E/Component/Index/All?pn=100013; Dielectric Type: X7R; OWNER: 3709; PRICE: 0; Part Type: CERAMIC; PartType: CERAMIC; ROHS: Yes; Tolerance: 10%; Voltage: 50V; barcode: 100013
DS8 = LED: LED Green Diffused 20mA 5V 570nm 0603; Agile Part Number: DIO-00003-01; Barcode: 300021; CIP Link: http://xsjbrdwin1/CIP-E/Component/Index/All?pn=300021; OWNER: 4001; PRICE: 0.1; Power: 2.2-20MA; ROHS: Yes; Rated Power: 2.2-20MA; Voltage: 2.2V
P1 = 7499111221A: Conn Rcpt RJ-45 RA 1000 Base-T LED TH Int Mag; Agile Part Number: CON-00268-01; Barcode: 420095; CIP Link: http://xsjbrdwin1/CIP-E/Component/Index/All?pn=420095; OWNER: 3709; PRICE: 8.75; Part Type: ETHERNET; PartType: ETHERNET; Pins: 16PINS; Pitch: 0.100; ROHS: YES
R202 R204-R214 R217-R219 R222-R229 = RES: Res 1K 1% 1/16W 100PPM 50V 0402; ALT_SYMBOLS: RESC100X50X40RND; ASSEMBLY_OPTIONS: DNP; Agile Part Number: RES-00027-01; Barcode: 200098; CIP Link: http://xsjbrdwin1/CIP-E/Component/Index/All?pn=200098; OWNER: 3709; PRICE: 0; Part Type: SMT - 1%; PartType: SMT - DNP; Power: DNP; ROHS: Yes; Rated Power: 1/16W; Tolerance: 1%; primarykey: 73
R215 R216 = RES: Res 2K21 1% 1/16W 100PPM 50V 0402; ALT_SYMBOLS: (0402,C402-25,RESC100X50X40L25NRND); Agile Part Number: RES-00023-01; Barcode: 200163; CIP Link: http://xsjbrdwin1/CIP-E/Component/Index/All?pn=200163; OWNER: 3709; PRICE: 0; Part Type: SMT - 1%; PartType: SMT - 1%; Power: 1/10W; ROHS: Yes; Rated Power: 1/16W; Tolerance: 1%; primarykey: 254
R234 = RES: Res 1M 5% 1/16W 200PPM 50V 0402; Agile Part Number: RES-00066-01; Barcode: 200013; CIP Link: http://xsjbrdwin1/CIP-E/Component/Index/All?pn=200013; OWNER: 4001; PRICE: 0; Part Type: SMT - 5%; PartType: SMT - 5%; Power: 1/10W; ROHS: Yes; Rated Power: 1/16W; Tolerance: 5%; primarykey: 4
R237 = RES: Res 11K 1% 1/16W 100PPM 50V 0402; ALT_SYMBOLS: RESC100X50X40RND; Agile Part Number: RES-00268-01; Barcode: 200289; CIP Link: http://xsjbrdwin1/CIP-E/Component/Index/All?pn=200289; OWNER: 3501; PRICE: 0; Part Type: SMT - 1%; PartType: SMT - 1%; Power: 1/10W; ROHS: Yes; Rated Power: 1/16W; Tolerance: 1%; primarykey: 156
R242-R244 = RES: Res 261R 1% 1/16W 100PPM 50V 0402; ALT_SYMBOLS: RESC100X50X40RND; Agile Part Number: RES-00086-01; Barcode: 200050; CIP Link: http://xsjbrdwin1/CIP-E/Component/Index/All?pn=200050; OWNER: 3501; PRICE: 0; Part Type: SMT - 1%; PartType: SMT - 1%; Power: 1/10W; ROHS: Yes; Rated Power: 1/16W; Tolerance: 1%; primarykey: 60
U33 = DP83867IRPAP_RGMII: IC PHY Ethernet Single 10/100/1000 Base-T 2.5V MII/GMII/RGMII HTQFP-64; Agile Part Number: ICS-00256-01; Barcode: 500382; CIP Link: http://xsjbrdwin1/CIP-E/Component/Index/All?pn=500382; Family: ETHERNET PHY; Part Type: ETHERNET PHY; ROHS: Yes
U34 = AND_GATE_SINGLE: IC AND Single 2-In 5V 50mA 3.6nSec SC70-5; Agile Part Number: ICS-00094-01; Barcode: 500077; CIP Link: http://xsjbrdwin1/CIP-E/Component/Index/All?pn=500077; Family: LOGIC; Part Type: LOGIC; ROHS: Yes
X5 = FA238: Xtal 25MHz 200uW 50R 18pF 80PPM 3225 SMT; Agile Part Number: XTL-00018-01; Barcode: 600035; CIP Link: http://xsjbrdwin1/CIP-E/Component/Index/All?pn=600035; OWNER: 3709; PRICE: 0.44; Part Type: CRYSTAL; PartType: CRYSTAL; ROHS: Yes
C307-C312 = CAP_NP: Cap Cer 10uF 20%  6.3V X6S 0402; ALT_SYMBOLS: CAPC100X50X55RND; Agile Part Number: CAP-00035-01; CIP Link: http://xsjbrdwin1/CIP-E/Component/Index/All?pn=100268; Dielectric Type: X6S; OWNER: 3670; PART_TYPE: CERAMIC; PKG_TYPE: 0805; PRICE: 0.04; Part Type: CERAMIC; PartType: CERAMIC; ROHS: Yes; Tolerance: 20%; Voltage: 6.3V; barcode: 100268
C313-C318 C320-C322 C324 C325 = CAP_NP: Cap Cer 100nF 10% 25V X5R 0402; ALT_SYMBOLS: CAPC100X50X55RND; Agile Part Number: CAP-00068-01; CIP Link: http://xsjbrdwin1/CIP-E/Component/Index/All?pn=100040; Dielectric Type: X5R; OWNER: 4001; PART_TYPE: CERAMIC; PKG_TYPE: 0402; PRICE: 0.01; Part Type: CERAMIC; PartType: CERAMIC; ROHS: Yes; Tolerance: 10%; Voltage: 25V; barcode: 100040
C319 = CAP_NP: Cap Cer 470nF 10% 10V X5R 0402; ALT_SYMBOLS: CAPC100X50X55RND; Agile Part Number: CAP-00054-01; CIP Link: http://xsjbrdwin1/CIP-E/Component/Index/All?pn=100022; Dielectric Type: X5R; OWNER: 4001; PART_TYPE: CERAMIC; PKG_TYPE: 0402; PRICE: 0.02; Part Type: CERAMIC; PartType: CERAMIC; ROHS: Yes; Tolerance: 10%; Voltage: 10V; barcode: 100022
C323 = CAP_NP: Cap Cer 2.2nF 10% 50V X7R 0402; ALT_SYMBOLS: CAPC100X50X55RND; Agile Part Number: CAP-00030-01; CIP Link: http://xsjbrdwin1/CIP-E/Component/Index/All?pn=100095; Dielectric Type: X7R; OWNER: 3709; PART_TYPE: CERAMIC; PKG_TYPE: 0402; PRICE: 0; Part Type: CERAMIC; PartType: CERAMIC; ROHS: Yes; Tolerance: 10%; Voltage: 50V; barcode: 100095
DS9 = LED: LED Blue Clear 30mA 5V 473nm Dom 0805; Agile Part Number: DIO-00104-01; Barcode: 70000028; CIP Link: http://xsjbrdwin1/CIP-E/Component/Index/All?pn=70000028
DS10 = LED: LED Green Diffused 20mA 5V 570nm 0603; Agile Part Number: DIO-00003-01; Barcode: 300021; CIP Link: http://xsjbrdwin1/CIP-E/Component/Index/All?pn=300021; OWNER: 4001; POWER: 2.2-20MA; PRICE: 0.1; ROHS: Yes; Rated Power: 2.2-20MA; Voltage: 2.2V
J26 = MSP_FET_IDC: Conn Hdr Male Vert 14 Pos 2x7 2.54mm P Black TH Shrouded; Agile Part Number: CON-00138-01; Barcode: 400069; CIP Link: http://xsjbrdwin1/CIP-E/Component/Index/All?pn=400069; OWNER: 3501; PART_TYPE: HEADER; PINS: 14PINS; PITCH: 0.100; PRICE: 1.05; Part Type: HEADER; PartType: HEADER; ROHS: Yes
J152 J153 = HDR_1X2: Conn Hdr Male Vert 2 Pos 1x2 2.54mm P Black TH; Agile Part Number: CON-00037-01; Barcode: 390102; CIP Link: http://xsjbrdwin1/CIP-E/Component/Index/All?pn=390102; OWNER: 4001; PRICE: 0.03; Part Type: HEADER; PartType: HEADER; Pins: 2PINS; Pitch: 0.100; ROHS: Yes
R248 R249 R255 R256 = RES: Res 0R 50mR 1A 0402; ALT_SYMBOLS: RESC100X50X40RND; Agile Part Number: RES-00010-01; Barcode: 200012; CIP Link: http://xsjbrdwin1/CIP-E/Component/Index/All?pn=200012; OWNER: 4001; PART_TYPE: SMT - 5%; PKG_TYPE: 0402; POWER: 1/10W; PRICE: 0.01; Part Type: SMT - 5%; PartType: SMT - 5%; ROHS: Yes; Tolerance: 5%; primarykey: 13
R250 R251 = RES: Res 261R 1% 1/16W 100PPM 50V 0402; ALT_SYMBOLS: RESC100X50X40RND; Agile Part Number: RES-00086-01; Barcode: 200050; CIP Link: http://xsjbrdwin1/CIP-E/Component/Index/All?pn=200050; OWNER: 3501; PART_TYPE: SMT - 1%; PKG_TYPE: 0402; POWER: 1/10W; PRICE: 0; Part Type: SMT - 1%; PartType: SMT - 1%; ROHS: Yes; Rated Power: 1/16W; Tolerance: 1%; primarykey: 60
R252 = RES: Res 10K 1% 1/16W 100PPM 50V 0402; ALT_SYMBOLS: RESC100X50X40RND; ASSEMBLY_OPTIONS: DNP; Agile Part Number: RES-00030-01; Barcode: 200025; CIP Link: http://xsjbrdwin1/CIP-E/Component/Index/All?pn=200025; OWNER: 3709; PART_TYPE: SMT - 5%; PKG_TYPE: 0402; POWER: DNP; PRICE: 0; Part Type: SMT - 1%; PartType: SMT - DNP; ROHS: Yes; Rated Power: 1/16W; Tolerance: 1%; primarykey: 73
R253 = RES: Res 10K 1% 1/16W 100PPM 50V 0402; ALT_SYMBOLS: RESC100X50X40RND; Agile Part Number: RES-00030-01; Barcode: 200025; CIP Link: http://xsjbrdwin1/CIP-E/Component/Index/All?pn=200025; OWNER: 4001; PART_TYPE: SMT - 5%; PKG_TYPE: 0402; POWER: 1/10W; PRICE: 0; Part Type: SMT - 1%; PartType: SMT - 1%; ROHS: Yes; Rated Power: 1/16W; Tolerance: 1%; primarykey: 1
R254 = RES: Res 47K5 1% 1/16W 100PPM 50V 0402; Agile Part Number: RES-00222-01; Barcode: 200237; CIP Link: http://xsjbrdwin1/CIP-E/Component/Index/All?pn=200237; OWNER: 3709; PART_TYPE: SMT - 1%; PKG_TYPE: 0402; POWER: 1/10W; PRICE: 0; Part Type: SMT - 1%; PartType: SMT - 1%; ROHS: Yes; Rated Power: 1/16W; Tolerance: 1%; primarykey: 279
SW6 = SW_DIP_5: Switch SPST-NO DIP 5 Pos 1.27mm P Flat 25mA 24Vdc Brown SMT; Agile Part Number: SWH-00029-01; Barcode: 440030; CIP Link: http://xsjbrdwin1/CIP-E/Component/Index/All?pn=440030; OWNER: 3670; PRICE: 2.55; Part Type: DIP; PartType: DIP; ROHS: Yes
SW7 = PUSHBUTTON-4: Switch SPST-NO Mom 50mA 50V 7.3mm H 100gf SMT; Agile Part Number: SWH-00014-01; Barcode: 440011; CIP Link: http://xsjbrdwin1/CIP-E/Component/Index/All?pn=440011; OWNER: 3709; PRICE: 0.25; Part Type: MOMENT; PartType: MOMENT; ROHS: Yes
U37 U39 = TXS0108E: IC Lvl Trans 8-Bit Bidir 110Mbps 1.2-5.5V 50mA TSSOP-20; Agile Part Number: ICS-00124-01; Barcode: 500123; CIP Link: http://xsjbrdwin1/CIP-E/Component/Index/All?pn=500123; Family: LEVEL TRANSLATOR; Part Type: LEVEL TRANSLATOR; ROHS: Yes
U38 = MSP430F5342: IC MCU 16 Bit 25MHz 128KB Flash VQFN-48; Agile Part Number: ICS-00199-01; Barcode: 500267; CIP Link: http://xsjbrdwin1/CIP-E/Component/Index/All?pn=500267; Family: MICROCONTROLLER; Part Type: MICROCONTROLLER; ROHS: Yes
U40 = AND_GATE_SINGLE: IC AND Single 2-In 5V 50mA 3.6nSec SC70-5; Agile Part Number: ICS-00094-01; Barcode: 500077; CIP Link: http://xsjbrdwin1/CIP-E/Component/Index/All?pn=500077; Family: LOGIC; OWNER: 10460; PART_TYPE: LOGIC; PRICE: 0.09; Part Type: LOGIC; ROHS: Yes
U41 = SN74AVC2T245: IC Lvl Trans 2-Bit Bidir 500Mbps 1.2-3.6V 50mA UQFN-10; Agile Part Number: ICS-00048-01; Barcode: 500012; CIP Link: http://xsjbrdwin1/CIP-E/Component/Index/All?pn=500012; Family: BUS TRANSCEIVER; Part Type: BUS TRANSCEIVER; ROHS: Yes
X6 = XTAL_32KHZ: Xtal 32.768KHz 1.0uW 50000R 12.5pF 20PPM 8.0x3.8mm SMT; Agile Part Number: XTL-00016-01; Barcode: 600025; CIP Link: http://xsjbrdwin1/CIP-E/Component/Index/All?pn=600025; OWNER: 3501; PART_TYPE: CRYSTAL; PRICE: 0.51; Part Type: CRYSTAL; PartType: CRYSTAL; ROHS: Yes
C327-C330 C332 C333 C335-C339 = CAP_NP: Cap Cer 1uF 10% 35V X5R 0402; ALT_SYMBOLS: CAPC100X50X60RND; Agile Part Number: CAP-00165-01; CIP Link: http://xsjbrdwin1/CIP-E/Component/Index/All?pn=100192; Dielectric Type: X5R; OWNER: 3709; PRICE: 0.04; Part Type: CERAMIC; PartType: CERAMIC; ROHS: Yes; Tolerance: 10%; Voltage: 35V; barcode: 100192
C331 = CAP_NP: Cap Cer 10uF 10% 25V X5R 1210; ALT_SYMBOLS: CAPC320X250X220RND; Agile Part Number: CAP-00113-01; CIP Link: http://xsjbrdwin1/CIP-E/Component/Index/All?pn=100123; Dielectric Type: X5R; OWNER: 3709; PRICE: 0.18; Part Type: CERAMIC; PartType: CERAMIC; ROHS: Yes; Tolerance: 10%; Voltage: 25V; barcode: 100123
C340 C341 = CAP_NP: Cap Cer 100uF 20% 6.3V X5R 1206; ALT_SYMBOLS: 1206; Agile Part Number: CAP-00061-01; CIP Link: http://xsjbrdwin1/CIP-E/Component/Index/All?pn=100029; Dielectric Type: X5R; OWNER: 3709; PRICE: 0.41; Part Type: CERAMIC; PartType: CERAMIC; ROHS: Yes; Tolerance: 20%; Voltage: 6.3V; barcode: 100029
U42 = NC7SZ66_SC70_5: IC Switch SPST Bus 0.3nSec 7R SC70-5; Agile Part Number: ICS-00079-01; Barcode: 500053; CIP Link: http://xsjbrdwin1/CIP-E/Component/Index/All?pn=500053; Family: ANALOG SWITCH; Part Type: ANALOG SWITCH; ROHS: Yes
J28 = ASP_184329_01: Conn Rcpt Female Vert 560 Pos 14x40 1.27mm P Black SMT; Agile Part Number: CON-00190-01; Barcode: 400137; CIP Link: http://xsjbrdwin1/CIP-E/Component/Index/All?pn=400137; OWNER: 3709; PRICE: 0; Part Type: HEADER; PartType: HEADER; Pins: 560PINS; Pitch: 1.27mm; ROHS: Yes

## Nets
GND: C239.2 C240.2 C241.2 C242.2 C243.2 C244.2 C245.2 C246.2 C247.2 C248.2 C249.2 C250.2 C251.2 C252.2 C253.2 C255.2 C256.2 C257.2 C258.2 C259.2 C260.2 C261.2 C262.2 C263.2 C264.2 C265.2 C266.2 C267.2 C268.2 C269.2 C270.1 C271.1 C272.1 C273.1 C274.2 C275.2 C276.2 C277.2 C278.2 C279.2 C280.2 C281.2 C282.2 C283.2 C284.2 C285.2 C286.2 C287.2 C288.2 C289.2 C290.2 C291.2 C292.2 C293.2 C294.2 C295.2 C296.2 C307.2 C308.2 C309.2 C310.2 C311.2 C312.2 C313.2 C314.2 C315.2 C316.2 C317.2 C318.2 C319.2 C320.2 C321.2 C322.2 C323.2 C324.2 C325.2 C326.2 C327.2 C328.2 C329.2 C330.2 C331.2 C332.2 C333.2 C334.2 C335.2 C336.2 C337.2 C338.2 C339.2 C340.2 C341.2 C1958.2 C1959.2 J25.1(P1) J25.3(P3) J25.5(P5) J25.7(P7) J25.9(P9) J25.11(P11) J25.13(P13) J26.9(GND) J28.C34(GA0) J28.D35(GA1) L11.1 P1.SH1 P1.SH2 R187.1 R195.2 R201.1 R217.2 R218.2 R219.2 R220.2 R221.2 R222.2 R223.2 R224.2 R225.2 R226.2 R227.2 R228.2 R229.2 R230.2 R231.2 R232.2 R233.2 R237.2 R238.2 R239.2 R240.2 R242.2 R243.2 R244.2 R245.2 R252.2 R253.2 SW6.1 SW6.2 SW6.3 SW6.4 SW6.5 SW7.3(P3) SW7.4(P4) U24.2(GND) U24.4(GND_TAB) U25.2(GND) U25.5(DIR) U26.2(GND) U27.1(1OE_B) U27.10(GND) U27.11(GND) U27.16(2OE_B) U28.2(GND) U29.1(GND1) U29.5(GND2) U29.10(AGND) U29.11(GND3) U29.13(TEST) U29.15(GND4) U29.25(GND5) U29.35(GND6) U29.47(GND7) U29.51(GND8) U30.2(GND) U31.5(VSS) U32.11(GND) U33.65(GND_PAD) U34.3(GND) U35.10(GND) U35.11(GND) U37.11(GND) U38.9(AVSS1) U38.11(DVSS1) U38.31(DVSS2) U38.38(DVSS3) U38.49(QFN_EPAD) U39.11(GND) U40.3(GND) U41.2(OE_B) U41.3(GND) U41.10(DIR1) U42.3(GND) U427.2(GND) X3.4(GND) X4.2(GND2) X4.4(GND1) X5.2(GND) X5.4(GND_3) ; also on sheet 3 4 5 7 8 9 10 11 12 13 14 16 17 18 19 20 21 22 23 24 32 33 34 35 36 37 38 39 40 41 42 43 44 45 46 47 48 49 50 51 52 53 54 55 56 57 58 59 60 61 62 63 64 65 66 67 68 69 70 71 72
VCC1V2: C257.1 C324.1 U32.2(VCCA) U32.10(OE) U41.1(DIR2) U41.7(VCCA) ; also on sheet 4 11 17 40 41 42 48 59 65 66 67 68
VCC1V8_BUS: C239.1 C241.1 C246.1 C255.1 C274.1 C277.1 C290.1 C291.1 C292.1 C293.1 C294.1 C295.1 C296.1 C317.1 C321.1 C1958.1 R202.1 R203.1 R204.1 R205.1 R206.1 R207.1 R208.1 R209.1 R210.1 R211.1 R212.1 R213.1 R214.1 R215.1 R216.1 R236.1 R246.1 U25.6(VCCB) U26.3(IN_P) U27.2(VCCB) U30.5(VCC) U33.23(VDDIO) U33.41(VDDIO) U33.57(VDDIO) U34.5(VCC) U35.3(VCCA) U37.2(VCCA) U37.10(OE) U39.2(VCCA) U39.10(OE) U427.3(VCCA) U427.6(OE) ; also on sheet 4 9 10 12 20 21 22 23 24 34 36 37 38 39 42 52 61 62 64
VCC12_SW: C331.1 C332.1 C333.1 J28.C35(12P0V_1) J28.C37(12P0V_2) ; also on sheet 31 43 44 45 47 48 49 50 51 52 57 58 62
VCC_TOOL_NC: J26.2(VCC_TOOL)
VCCO_JTAG_ON: U26.1(OUT) U29.21(ADBUS4)
8A34001_CLK5_IN_N: J28.D5(GBTCLK0_M2C_N) ; also on sheet 38
8A34001_CLK5_IN_P: J28.D4(GBTCLK0_M2C_P) ; also on sheet 38
BOARD_ID0: R252.1 U38.37(P5_7/TB0_1)
BOARD_ID1: R253.1 U38.40(P5_3/XT2OUT)
ENET_COL_GPIO: R210.2 R222.1 U33.55(COL_GPIO)
ENET_CRS: R211.2 R227.1 U33.56(CRS)
ENET_LED_0: R214.2 R229.1 U33.63(LED_0) U35.8(2A1)
ENET_LED_0_LS: P1.14(RIGHT_GREEN_AN) U35.13(2B1)
ENET_LED_0_LS_R: P1.13(RIGHT_GREEN_CA) R242.1
ENET_LED_1: R213.2 R228.1 U33.62(LED_1) U35.7(1A2)
ENET_LED_1_LS: DS8.2 U35.14(1B2)
ENET_LED_2: R212.2 R223.1 U33.61(LED_2) U35.6(1A1)
ENET_LED_2_LS: P1.16(LEFT_GREEN_AN) U35.15(1B1)
ENET_LED_2_LS_R: P1.15(LEFT_GREEN_CA) R244.1
ENET_RESET_B: R236.2 U33.59(RESET_B) U34.4(Y)
ENET_RX_D4: R204.2 R225.1 U33.48(RX_D4)
ENET_RX_D5: R205.2 R217.1 U33.49(RX_D5)
ENET_RX_D6: R206.2 R218.1 U33.50(RX_D6)
ENET_RX_D7: R207.2 R226.1 U33.51(RX_D7)
ENET_RX_ER_GPIO: R209.2 R219.1 U33.54(RX_ER_GPIO)
ENET_TD_A_N: P1.10(TD0_N) U33.3(TD_M_A)
ENET_TD_A_P: P1.11(TD0_P) U33.2(TD_P_A)
ENET_TD_B_N: P1.5(TD1_N) U33.6(TD_M_B)
ENET_TD_B_P: P1.4(TD1_P) U33.5(TD_P_B)
ENET_TD_C_N: P1.2(TD2_N) U33.11(TD_M_C)
ENET_TD_C_P: P1.3(TD2_P) U33.10(TD_P_C)
ENET_TD_D_N: P1.9(TD3_N) U33.14(TD_M_D)
ENET_TD_D_P: P1.8(TD3_P) U33.13(TD_P_D)
ENET_TX_D4: R233.1 U33.34(TX_D4)
ENET_TX_D5: R232.1 U33.33(TX_D5)
ENET_TX_D6: R231.1 U33.32(TX_D6)
ENET_TX_D7: R230.1 U33.31(TX_D7)
ENET_VDDA_17_NC: U33.17(VDDA1P8)
ENET_VDDA_64_NC: U33.64(VDDA1P8)
ENET_XI: C275.1 R234.1 U33.19(XI) X5.3(X2)
ENET_XO: C276.1 R234.2 U33.18(XO) X5.1(X1)
FMCP_HSPC_DP0_C2M_N: J28.C3(DP0_C2M_N) ; also on sheet 6
FMCP_HSPC_DP0_C2M_P: J28.C2(DP0_C2M_P) ; also on sheet 6
FMCP_HSPC_DP0_M2C_N: J28.C7(DP0_M2C_N) ; also on sheet 6
FMCP_HSPC_DP0_M2C_P: J28.C6(DP0_M2C_P) ; also on sheet 6
FMCP_HSPC_DP1_C2M_N: J28.A23(DP1_C2M_N) ; also on sheet 6
FMCP_HSPC_DP1_C2M_P: J28.A22(DP1_C2M_P) ; also on sheet 6
FMCP_HSPC_DP1_M2C_N: J28.A3(DP1_M2C_N) ; also on sheet 6
FMCP_HSPC_DP1_M2C_P: J28.A2(DP1_M2C_P) ; also on sheet 6
FMCP_HSPC_DP2_C2M_N: J28.A27(DP2_C2M_N) ; also on sheet 6
FMCP_HSPC_DP2_C2M_P: J28.A26(DP2_C2M_P) ; also on sheet 6
FMCP_HSPC_DP2_M2C_N: J28.A7(DP2_M2C_N) ; also on sheet 6
FMCP_HSPC_DP2_M2C_P: J28.A6(DP2_M2C_P) ; also on sheet 6
FMCP_HSPC_DP3_C2M_N: J28.A31(DP3_C2M_N) ; also on sheet 6
FMCP_HSPC_DP3_C2M_P: J28.A30(DP3_C2M_P) ; also on sheet 6
FMCP_HSPC_DP3_M2C_N: J28.A11(DP3_M2C_N) ; also on sheet 6
FMCP_HSPC_DP3_M2C_P: J28.A10(DP3_M2C_P) ; also on sheet 6
FMCP_HSPC_DP4_C2M_N: J28.A35(DP4_C2M_N) ; also on sheet 12
FMCP_HSPC_DP4_C2M_P: J28.A34(DP4_C2M_P) ; also on sheet 12
FMCP_HSPC_DP4_M2C_N: J28.A15(DP4_M2C_N) ; also on sheet 12
FMCP_HSPC_DP4_M2C_P: J28.A14(DP4_M2C_P) ; also on sheet 12
FMCP_HSPC_DP5_C2M_N: J28.A39(DP5_C2M_N) ; also on sheet 12
FMCP_HSPC_DP5_C2M_P: J28.A38(DP5_C2M_P) ; also on sheet 12
FMCP_HSPC_DP5_M2C_N: J28.A19(DP5_M2C_N) ; also on sheet 12
FMCP_HSPC_DP5_M2C_P: J28.A18(DP5_M2C_P) ; also on sheet 12
FMCP_HSPC_DP6_C2M_N: J28.B37(DP6_C2M_N) ; also on sheet 12
FMCP_HSPC_DP6_C2M_P: J28.B36(DP6_C2M_P) ; also on sheet 12
FMCP_HSPC_DP6_M2C_N: J28.B17(DP6_M2C_N) ; also on sheet 12
FMCP_HSPC_DP6_M2C_P: J28.B16(DP6_M2C_P) ; also on sheet 12
FMCP_HSPC_GBTCLK1_M2C_N: J28.B21(GBTCLK1_M2C_N) ; also on sheet 12
FMCP_HSPC_GBTCLK1_M2C_P: J28.B20(GBTCLK1_M2C_P) ; also on sheet 12
FMCP_HSPC_IIC_SCL: J28.C30(SCL) ; also on sheet 23
FMCP_HSPC_IIC_SDA: J28.C31(SDA) ; also on sheet 23
FMCP_HSPC_PG_M2C: J28.F1(PG_M2C) R257.2
FMCP_HSPC_PRSNT_M2C_B: U42.4(OE) ; also on sheet 22 30 31
FMCP_HSPC_TDO: J25.8(P8) J28.D31(TDO) R191.2 R194.2 U29.18(ADBUS2) U42.2(B)
FPGA_TCK: R188.2 ; also on sheet 10
FPGA_TDI: U27.13(2B1) ; also on sheet 10
FPGA_TDO_FMC_TDI: U25.4(B) ; also on sheet 10
FPGA_TDO_FMC_TDI_LS: J28.D30(TDI) U25.3(A) U42.1(A)
FPGA_TMS: U27.15(1B1) ; also on sheet 10
FT4232_TCK: J25.6(P6) J28.D29(TCK) R190.2 U27.7(1A2) U29.16(ADBUS0)
FT4232_TDI: J25.10(P10) R192.2 U27.8(2A1) U29.17(ADBUS1)
FT4232_TMS: J25.4(P4) J28.D33(TMS) R189.2 U27.6(1A1) U29.19(ADBUS3)
FTDI_PS_POR_B: U28.1(A1) U29.23(ADBUS6)
FTDI_PS_SRST_B: U28.3(A2) U29.24(ADBUS7)
GEM3_EXP_RESET_B: R235.2 U34.2(B) ; also on sheet 22
GPIO_LED_0: J153.2(P2) ; also on sheet 37
GPIO_LED_1: J152.2(P2) ; also on sheet 37
I2C0_SCL: U38.23(P3_1/UCB0SOMI/UCB0SCL) ; also on sheet 22
I2C0_SDA: U38.22(P3_0/UCB0SIMO/UCB0SDA) ; also on sheet 22
I2C1_SCL: R249.2 ; also on sheet 23
I2C1_SDA: R248.2 ; also on sheet 23
LS_UART0_RXD_IN: U29.27(BDBUS1) U427.1(B2)
LS_UART0_TXD_OUT: U29.26(BDBUS0) U427.8(B1)
LS_UART2_CTS_B: U29.41(CDBUS3) U32.14(B6)
LS_UART2_RTS_B: U29.40(CDBUS2) U32.15(B5)
LS_UART2_RXD_IN: U29.39(CDBUS1) U32.16(B4)
LS_UART2_TXD_OUT: U29.38(CDBUS0) U32.17(B3)
MIO13_PS_GPIO2: U37.9(A8) ; also on sheet 9
MIO26_PMU_INPUT: U27.12(2B2) ; also on sheet 9
MIO26_PMU_INPUT_LS: U27.9(2A2) ; also on sheet 22
MIO32_PMU_GPO0: U37.1(A1) ; also on sheet 9
MIO33_PMU_GPO1: U37.3(A2) ; also on sheet 9
MIO34_PMU_GPO2: U37.4(A3) ; also on sheet 9
MIO35_PMU_GPO3: U37.5(A4) ; also on sheet 9
MIO36_PMU_GPO4: U37.6(A5) ; also on sheet 9
MIO37_PMU_GPO5: U37.7(A6) ; also on sheet 9
MIO38_PS_GPIO1: U37.8(A7) ; also on sheet 9
MIO64_ENET_TX_CLK: U33.40(GTX_CLK) ; also on sheet 9
MIO65_ENET_TX_D0: U33.38(TX_D0_SGMII_SIN) ; also on sheet 9
MIO66_ENET_TX_D1: U33.37(TX_D1_SGMII_SIP) ; also on sheet 9
MIO67_ENET_TX_D2: U33.36(TX_D2) ; also on sheet 9
MIO68_ENET_TX_D3: U33.35(TX_D3) ; also on sheet 9
MIO69_ENET_TX_CTRL: U33.52(TX_EN_TX_CTRL) ; also on sheet 9
MIO70_ENET_RX_CLK: U33.43(RX_CLK) ; also on sheet 9
MIO71_ENET_RX_D0: R202.2 R220.1 U33.44(RX_D0_SGMII_COP) ; also on sheet 9
MIO72_ENET_RX_D1: U33.45(RX_D1_SGMII_CON) ; also on sheet 9
MIO73_ENET_RX_D2: R203.2 R224.1 U33.46(RX_D2_SGMII_SOP) ; also on sheet 9
MIO74_ENET_RX_D3: U33.47(RX_D3_SGMII_SON) ; also on sheet 9
MIO75_ENET_RX_CTRL: R208.2 R221.1 U33.53(RX_DV_RX_CTRL) ; also on sheet 9
MIO76_ENET_MDC: U33.20(MDC) ; also on sheet 9
MIO77_ENET_MDIO: R216.2 U33.21(MDIO) ; also on sheet 9
MSP430_FET_TCK: J26.7(TCK) U38.45(PJ_3/TCK)
MSP430_FET_TDI: J26.3(TDI) U38.43(PJ_1/TDI/TCLK)
MSP430_FET_TDO: J26.1(TDO) U38.42(PJ_0/TDO)
MSP430_FET_TMS: J26.5(TMS) U38.44(PJ_2/TMS)
MSP430_GPIO_PL_0: U38.27(P4_0/PM_UCB1STE/PM_UCA1CLK) U39.20(B1)
MSP430_GPIO_PL_0_LS: U39.1(A1) ; also on sheet 5
MSP430_GPIO_PL_1: U38.30(P4_3/PM_UCB1CLK/PM_UCA1STE) U39.18(B2)
MSP430_GPIO_PL_1_LS: U39.3(A2) ; also on sheet 5
MSP430_GPIO_PL_2: U38.35(P4_6/PM_NONE) U39.17(B3)
MSP430_GPIO_PL_2_LS: U39.4(A3) ; also on sheet 5
MSP430_GPIO_PL_3: U38.36(P4_7/PM_NONE) U39.16(B4)
MSP430_GPIO_PL_3_LS: U39.5(A4) ; also on sheet 5
MSP430_GPIO_PS0: U37.13(B7) U38.19(P1_6/TA1CLK/CBOUT)
MSP430_GPIO_PS1: U37.12(B8) U38.20(P1_7/TA1_0)
MSP430_LED0: R250.2 U38.21(P2_7/UCB0STE/UCA0CLK)
MSP430_LED1: R251.2 U38.24(P3_2/UCB0CLK/UCA0STE)
MSP430_PMU_GPO0: U37.20(B1) U38.13(P1_0/TA0CLK/ACLK)
MSP430_PMU_GPO1: U37.18(B2) U38.14(P1_1/TA0_0)
MSP430_PMU_GPO2: U37.17(B3) U38.15(P1_2/TA0_1)
MSP430_PMU_GPO3: U37.16(B4) U38.16(P1_3/TA0_2)
MSP430_PMU_GPO4: U37.15(B5) U38.17(P1_4/TA0_3)
MSP430_PMU_GPO5: U37.14(B6) U38.18(P1_5/TA0_4)
MSP430_RST_B: J153.1(P1) R255.2 U40.1(A) U40.2(B)
MSP430_RST_NMI: U38.46(RST_B/NMI/SBWTDIO) U40.4(Y)
MSP430_SW0: SW6.10 U38.47(P6_1/CB1/A1)
MSP430_SW1: SW6.9 U38.48(P6_2/CB2/A2)
MSP430_SW2: SW6.8 U38.1(P6_3/CB3/A3)
MSP430_SW3: SW6.7 U38.2(P6_4/CB4/A4)
MSP430_SW4: SW6.6 U38.3(P6_5/CB5/A5)
MSP430_TEST: J152.1(P1) R256.2 U38.41(TEST/SBWTCK)
MSP430_UCA1_RXD: U38.34(P4_5/PM_UCA1RXD/PM_UCA1SOMI) U41.4(B2)
MSP430_UCA1_RXD_LS: U41.9(A2) ; also on sheet 4
MSP430_UCA1_TXD: U38.33(P4_4/PM_UCA1TXD/PM_UCA1SIMO) U41.5(B1)
MSP430_UCA1_TXD_LS: U41.8(A1) ; also on sheet 4
MSP430_UCB1_SCL_R: R249.1 U38.29(P4_2/PM_UCB1SOMI/PM_UCB1SCL)
MSP430_UCB1_SDA_R: R248.1 U38.28(P4_1/PM_UCB1SIMO/PM_UCB1SDA)
PC4_PS_SRST_B: J25.14(P14) R193.2 U30.1(A1)
PS_POR_B: U28.6(Y1) U34.1(A) ; also on sheet 10 20 24
PS_SRST_B: U28.4(Y2) U30.6(Y1) ; also on sheet 10
UART0_RXD_MIO19_TXD: U427.4(A2) ; also on sheet 9
UART0_TXD_MIO18_RXD: U427.5(A1) ; also on sheet 9
UART2_CTS_B: U32.7(A6) ; also on sheet 4
UART2_RTS_B: U32.6(A5) ; also on sheet 4
UART2_RXD_FPGA_TXD: U32.5(A4) ; also on sheet 4
UART2_TXD_FPGA_RXD: U32.4(A3) ; also on sheet 4
UART3_RXD_I_MSP430_UCA0_TXD: U29.52(DDBUS1) U38.25(P3_3/UCA0TXD/UCA0SIMO)
UART3_TXD_O_MSP430_UCA0_RXD: U29.48(DDBUS0) U38.26(P3_4/UCA0RXD/UCA0SOMI)
USB_JTAG_DM_N: J24.2(D_N) U29.7(DM) X3.2(D_N)
USB_JTAG_DM_P: J24.3(D_P) U29.8(DP) X3.1(D_P)
USB_JTAG_FLTR: C243.1 C252.1 C253.1 L10.1 U24.1(IN)
USB_JTAG_VBUS: C254.1 J24.1(VBUS) L10.2 X3.6(VBUS)
USB_JTAG_VCORE: C259.1 C260.1 C261.1 C262.1 U29.12(VCORE1) U29.37(VOCRE2) U29.49(VREGOUT) U29.64(VCORE3)
USB_JTAG_VPHY: C247.1 C248.1 L8.2 U29.4(VPHY)
USB_JTAG_VPLL: C249.1 C250.1 L9.2 U29.9(VPLL)
USB_POWERED_VCCIO: C240.1 C244.1 C251.1 C256.1 C258.1 C264.1 C265.1 C266.1 C267.1 C268.1 C1959.1 L8.1 L9.1 R186.1 R194.1 R196.1 R197.1 R198.1 R199.1 U24.3(OUT) U26.5(VCC) U28.5(VCC) U29.20(VCCIO1) U29.31(VCCIO2) U29.42(VCCIO3) U29.50(VREGIN) U29.56(VCCIO4) U31.8(VCC) U32.19(VCCB) U427.7(VCCB)
UTIL_1V13: C283.1 C284.1 C285.1 C286.1 C287.1 C288.1 C289.1 R241.2 U33.8(VDD1P1) U33.29(VDD1P1) U33.42(VDD1P1) U33.58(VDD1P1) ; also on sheet 47
UTIL_2V5: C279.1 C280.1 C281.1 C282.1 U33.4(VDDA2P5) U33.12(VDDA2P5) ; also on sheet 40 47 49 65 66 67 68
UTIL_3V3: C242.1 C245.1 C278.1 C307.1 C308.1 C309.1 C310.1 C311.1 C312.1 C313.1 C314.1 C315.1 C316.1 C318.1 C320.1 C322.1 C325.1 C334.1 C335.1 C336.1 C337.1 C338.1 C339.1 C340.1 C341.1 DS9.2 DS10.2 J25.2(P2) J26.4(VCC_DUT) J28.C39(3P3V_1) J28.D32(3P3VAUX) J28.D36(3P3V_2) J28.D38(3P3V_3) J28.D40(3P3V_4) R91.1 R189.1 R190.1 R191.1 R192.1 R193.1 R235.1 R254.1 R257.1 U25.1(VCCA) U27.3(VCCA) U35.2(VCCB) U37.19(VCCB) U38.6(AVCC1) U38.10(DVCC1) U38.32(DVCC2) U39.19(VCCB) U40.5(VCC) U41.6(VCCB) U42.5(VCC) ; also on sheet 9 10 20 22 23 24 30 31 33 34 36 37 40 42 43 44 45 47 49 51 53 54 55 56 57 59 60 61 64
VADJ_FMC: C326.1 C327.1 C328.1 C329.1 C330.1 J28.E39(VADJ_1) J28.F40(VADJ_2) J28.G39(VADJ_3) ; also on sheet 30 47
VADJ_FMC_PGOOD: J28.D1(PG_C2M) ; also on sheet 47 60
N23440: C319.1 U38.12(VCORE)
N23494: DS10.1 R251.1
N23644: U38.7(P5_4/XIN) X6.1(X1)
N23652: U38.8(P5_5/XOUT) X6.4(X2)
N23668: C323.1 J26.11(RST_B) R254.2 R255.1 SW7.1(P1) SW7.2(P2)
N23694: J26.8(TEST) R256.1
N23734: DS9.1 R250.1
N17321304: J24.4(ID) X3.3(ID)
N17346204: C269.1 U29.3(OSCO) X4.3(X3)
N17346209: C263.1 U29.2(OSCI) X4.1(X1)
N17355660: R91.2 U27.4(1DIR) U27.5(2DIR)
N17691108: R199.2 U29.63(EECS) U31.1(CS)
N17691111: R198.2 U29.62(EECLK) U31.2(CLK)
N17691127: R200.2 U29.61(EEDATA) U31.3(DI)
N17691166: R197.2 R200.1 U31.4(DO)
N21263458: C254.2 J24.5(GND) L11.2
N21263681: J24.6(SHLD1) J24.7(SHLD2) J24.8(SHLD3) J24.9(SHLD4) J24.10(SHLD5) J24.11(SHLD6) R195.1
N21269504: R201.2 U29.6(REF)
N21269608: R196.2 U29.14(RESET#)
N21275902: R186.2 R187.2 U26.4(IN_N)
N21286124: R188.1 U27.14(1B2)
N21289850: R241.1 U33.24(JTAG_TRST_B)
N21289852: R240.1 U33.25(JTAG_CLK)
N21289854: R239.1 U33.27(JTAG_TMS)
N21289871: R238.1 U33.28(JTAG_TDI)
N21291247: C273.2 P1.7(CT3)
N21291254: C271.2 P1.6(CT1)
N21291257: C270.2 P1.12(CT0)
N21291262: C272.2 P1.1(CT2)
N21296484: DS8.1 R243.1
N21297004: R245.1 U35.1(1OE_B) U35.9(2A2) U35.16(2OE_B)
N21297236: R246.2 U35.4(1DIR) U35.5(2DIR)
N21298326: R215.2 U33.60(INT_PWDN)
N21298760: R237.1 U33.15(RBIAS)

Not connected (* = marked no-connect by the designer): J25 12(P12)*; J26 6(NC1)* 10(NC2)* 12(NC3)* 13(NC4)* 14(NC5)*; J28 B1(CLK_DIR)* B4(DP9_M2C_P)* B5(DP9_M2C_N)* B8(DP8_M2C_P)* B9(DP8_M2C_N)* B12(DP7_M2C_P)* B13(DP7_M2C_N)* B24(DP9_C2M_P)* B25(DP9_C2M_N)* B28(DP8_C2M_P)* B29(DP8_C2M_N)* B32(DP7_C2M_P)* B33(DP7_C2M_N)* B40(RES0)* C10(LA06_P)* C11(LA06_N)* C14(LA10_P)* C15(LA10_N)* C18(LA14_P)* C19(LA14_N)* C22(LA18_P_CC)* C23(LA18_N_CC)* C26(LA27_P)* C27(LA27_N)* D8(LA01_P_CC)* D9(LA01_N_CC)* D11(LA05_P)* D12(LA05_N)* D14(LA09_P)* D15(LA09_N)* D17(LA13_P)* D18(LA13_N)* D20(LA17_P_CC)* D21(LA17_N_CC)* D23(LA23_P)* D24(LA23_N)* D26(LA26_P)* D27(LA26_N)* D34(TRST_L)* E2(HA01_P_CC)* E3(HA01_N_CC)* E6(HA05_P)* E7(HA05_N)* E9(HA09_P)* E10(HA09_N)* E12(HA13_P)* E13(HA13_N)* E15(HA16_P)* E16(HA16_N)* E18(HA20_P)* E19(HA20_N)* E21(HB03_P)* E22(HB03_N)* E24(HB05_P)* E25(HB05_N)* E27(HB09_P)* E28(HB09_N)* E30(HB13_P)* E31(HB13_N)* E33(HB19_P)* E34(HB19_N)* E36(HB21_P)* E37(HB21_N)* F4(HA00_P_CC)* F5(HA00_N_CC)* F7(HA04_P)* F8(HA04_N)* F10(HA08_P)* F11(HA08_N)* F13(HA12_P)* F14(HA12_N)* F16(HA15_P)* F17(HA15_N)* F19(HA19_P)* F20(HA19_N)* F22(HB02_P)* F23(HB02_N)* F25(HB04_P)* F26(HB04_N)* F28(HB08_P)* F29(HB08_N)* F31(HB12_P)* F32(HB12_N)* F34(HB16_P)* F35(HB16_N)* F37(HB20_P)* F38(HB20_N)* G2(CLK1_M2C_P)* G3(CLK1_M2C_N)* G6(LA00_P_CC)* G7(LA00_N_CC)* G9(LA03_P)* G10(LA03_N)* G12(LA08_P)* G13(LA08_N)* G15(LA12_P)* G16(LA12_N)* G18(LA16_P)* G19(LA16_N)* G21(LA20_P)* G22(LA20_N)* G24(LA22_P)* G25(LA22_N)* G27(LA25_P)* G28(LA25_N)* G30(LA29_P)* G31(LA29_N)* G33(LA31_P)* G34(LA31_N)* G36(LA33_P)* G37(LA33_N)*; U29 22(ADBUS5)* 28(BDBUS2)* 29(BDBUS3)* 30(BDBUS4)* 32(BDBUS5)* 33(BDBUS6)* 34(BDBUS7)* 36(SUSPEND#)* 43(CDBUS4)* 44(CDBUS5)* 45(CDBUS6)* 46(CDBUS7)* 53(DDBUS2)* 54(DDBUS3)* 55(DDBUS4)* 57(DDBUS5)* 58(DDBUS6)* 59(DDBUS7)* 60(PWREN#)*; U30 3(A2)* 4(Y2)*; U31 6(ORG_NC)* 7(NC)*; U32 1(A1)* 3(A2)* 8(A7)* 9(A8)* 12(B8)* 13(B7)* 18(B2)* 20(B1)*; U33 1(RESERVED1)* 7(RESERVED2)* 9(RESERVED3)* 16(RESERVED4)* 22(CLK_OUT)* 26(JTAG_TDO)* 30(TX_CLK)* 39(TX_ER)*; U35 12(2B2)*; U38 4(P5_0/VREF+/VeREF+/A8)* 5(P5_1/VREF-/VeREF-/A9)* 39(P5_2/XT2IN)*; U39 6(A5)* 7(A6)* 8(A7)* 9(A8)* 12(B8)* 13(B7)* 14(B6)* 15(B5)*; X3 5(NC)*; X6 2(NC2)* 3(NC3)*

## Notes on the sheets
sheet 26
- STRAP CONFIGURATION RESISTORS: SEE DP83867 DATASHEET
- THESE CAPACITORS ARE PLACED AS CLOSE AS
- POSSIBLE TO THEIR RESPECTIVE DP83867 PINS
sheet 27
- 2
- 2 PLACES
- CONTROLLER RESET
- MANUAL
- RESET
sheet 28
- ANSI/VITA 57.4 - Draft OCT 2015
- When OE = 1
- Switch is Closed
sheet 29
- ANSI/VITA 57.4 - Draft OCT 2015
